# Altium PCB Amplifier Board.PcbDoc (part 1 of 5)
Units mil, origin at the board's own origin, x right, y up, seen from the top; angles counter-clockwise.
Board outline 6000 x 4000 mil, 6 copper layers (Top Layer, GND, VCC, InternalPlane3, InternalPlane4, Bottom Layer); 880 components, 519 nets, 2020 pads, 372 vias.
Unrouted connection lines stored in the file: 585.
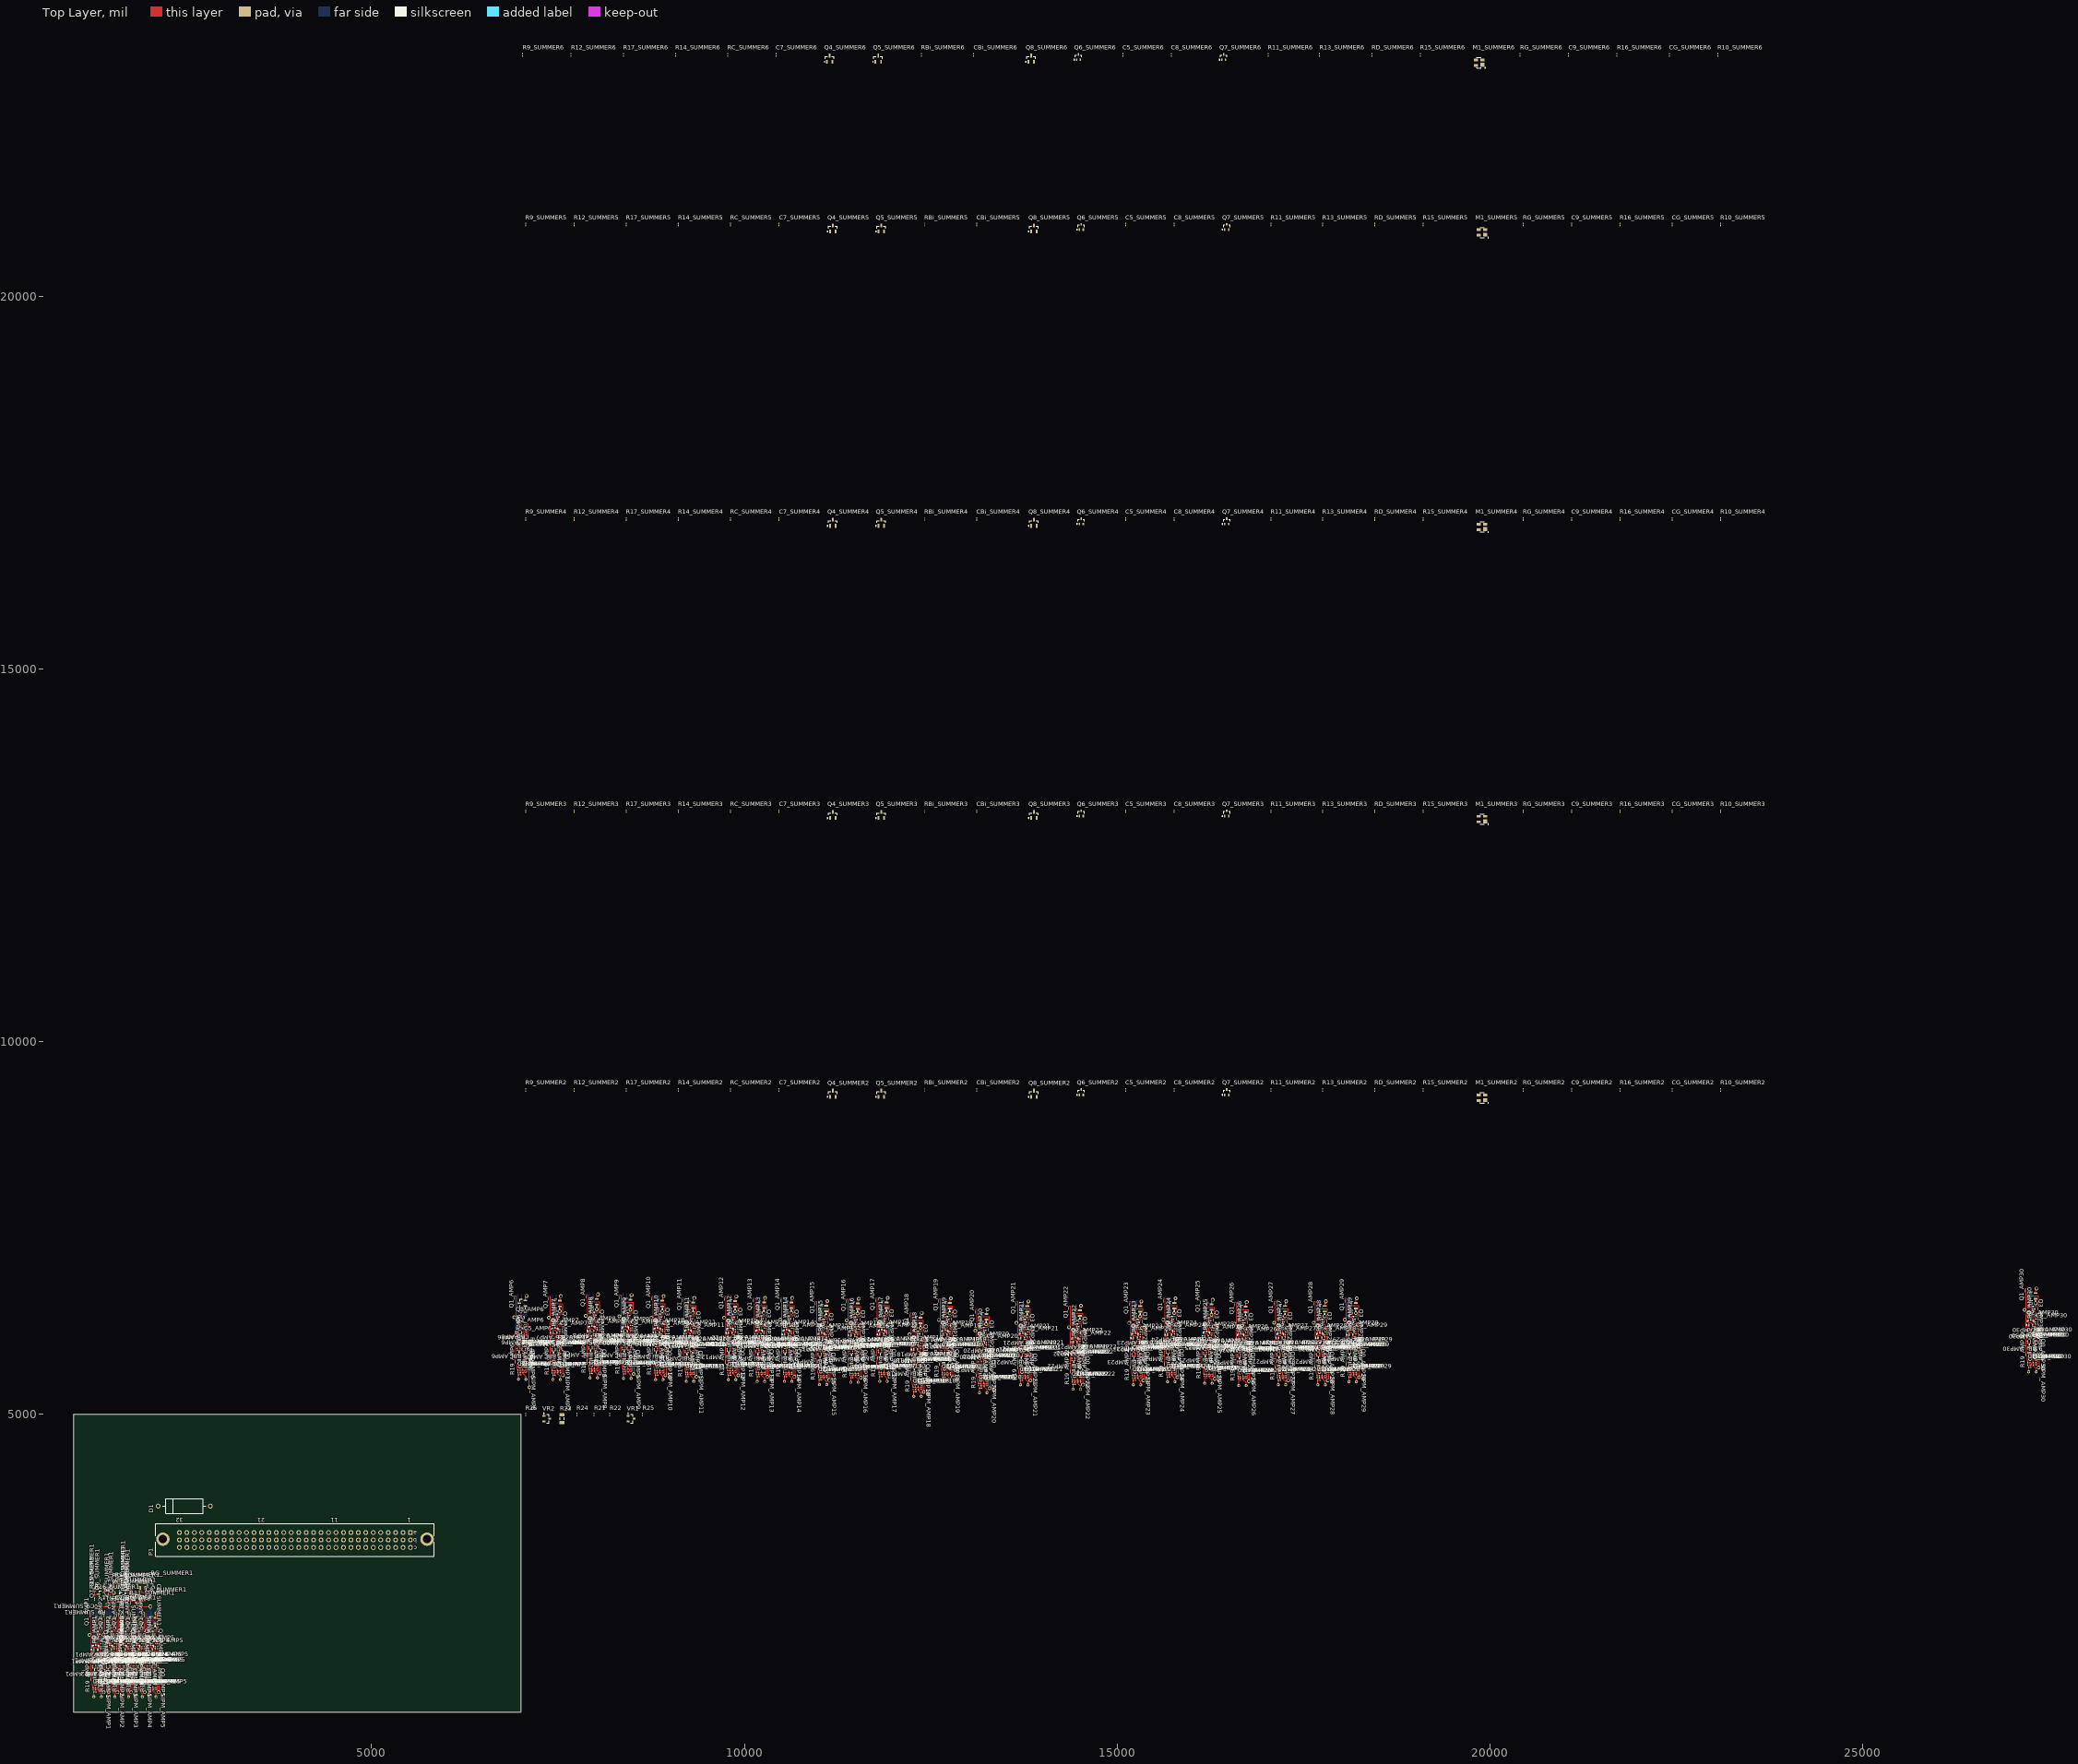
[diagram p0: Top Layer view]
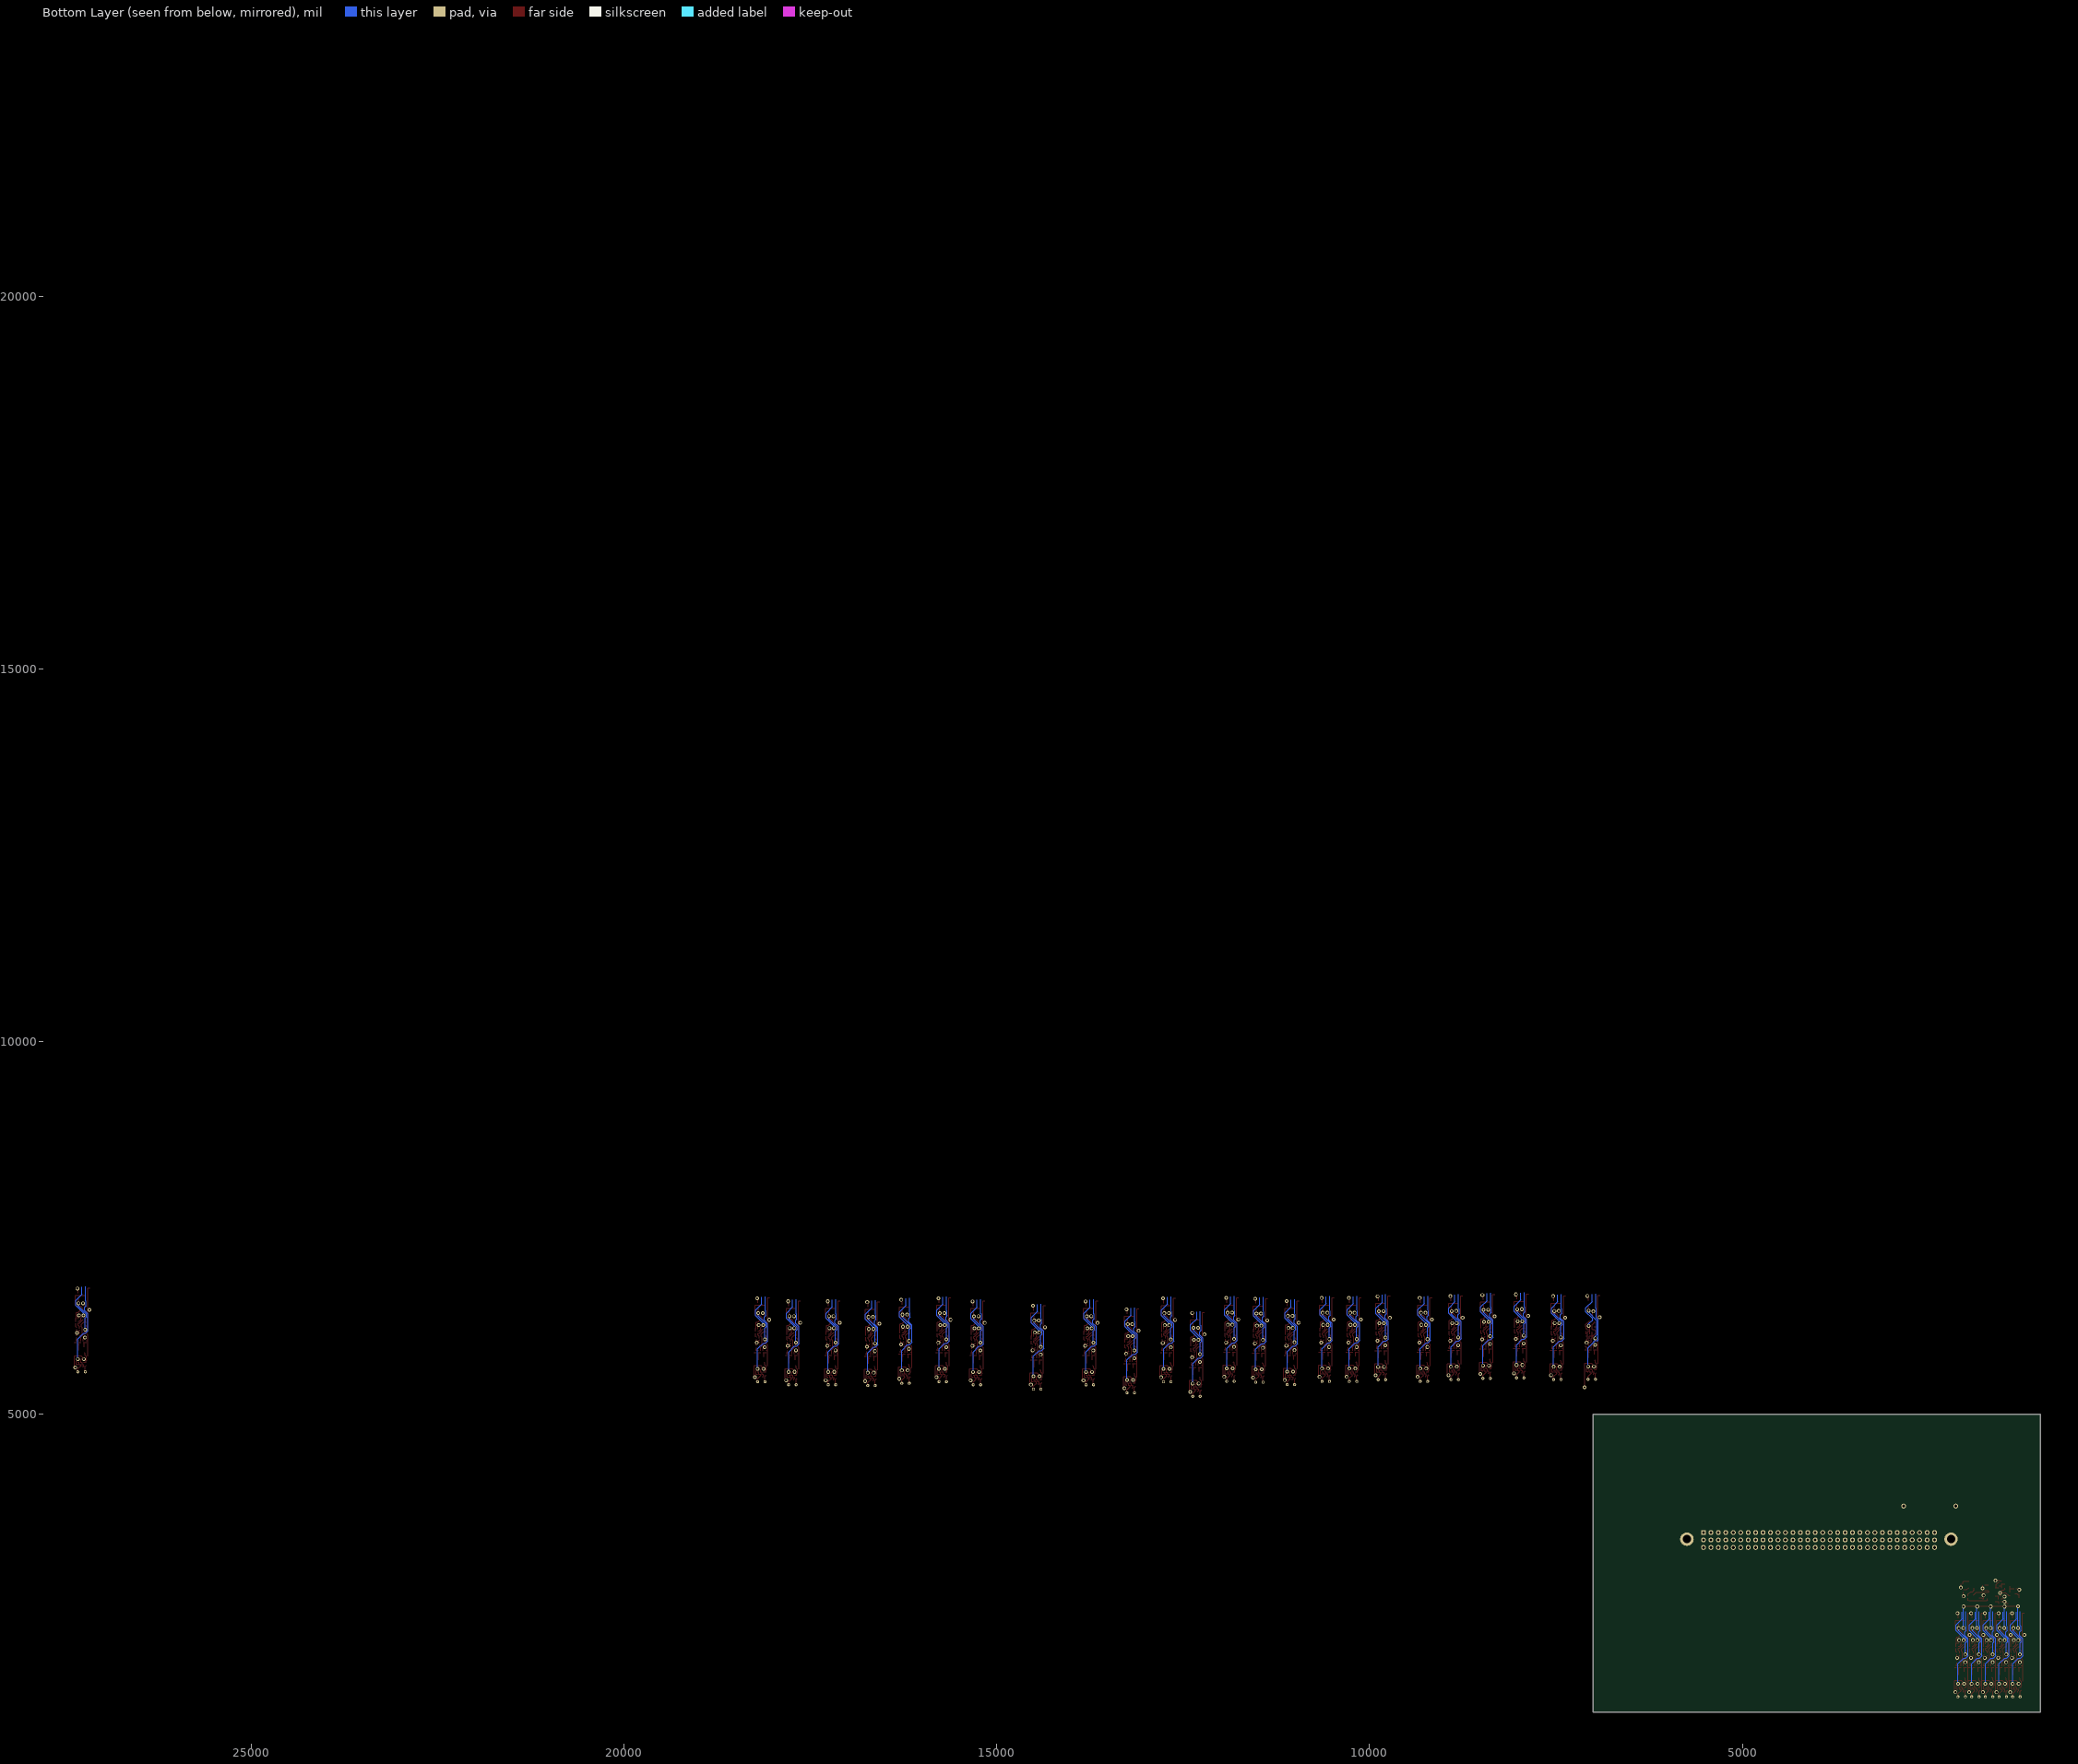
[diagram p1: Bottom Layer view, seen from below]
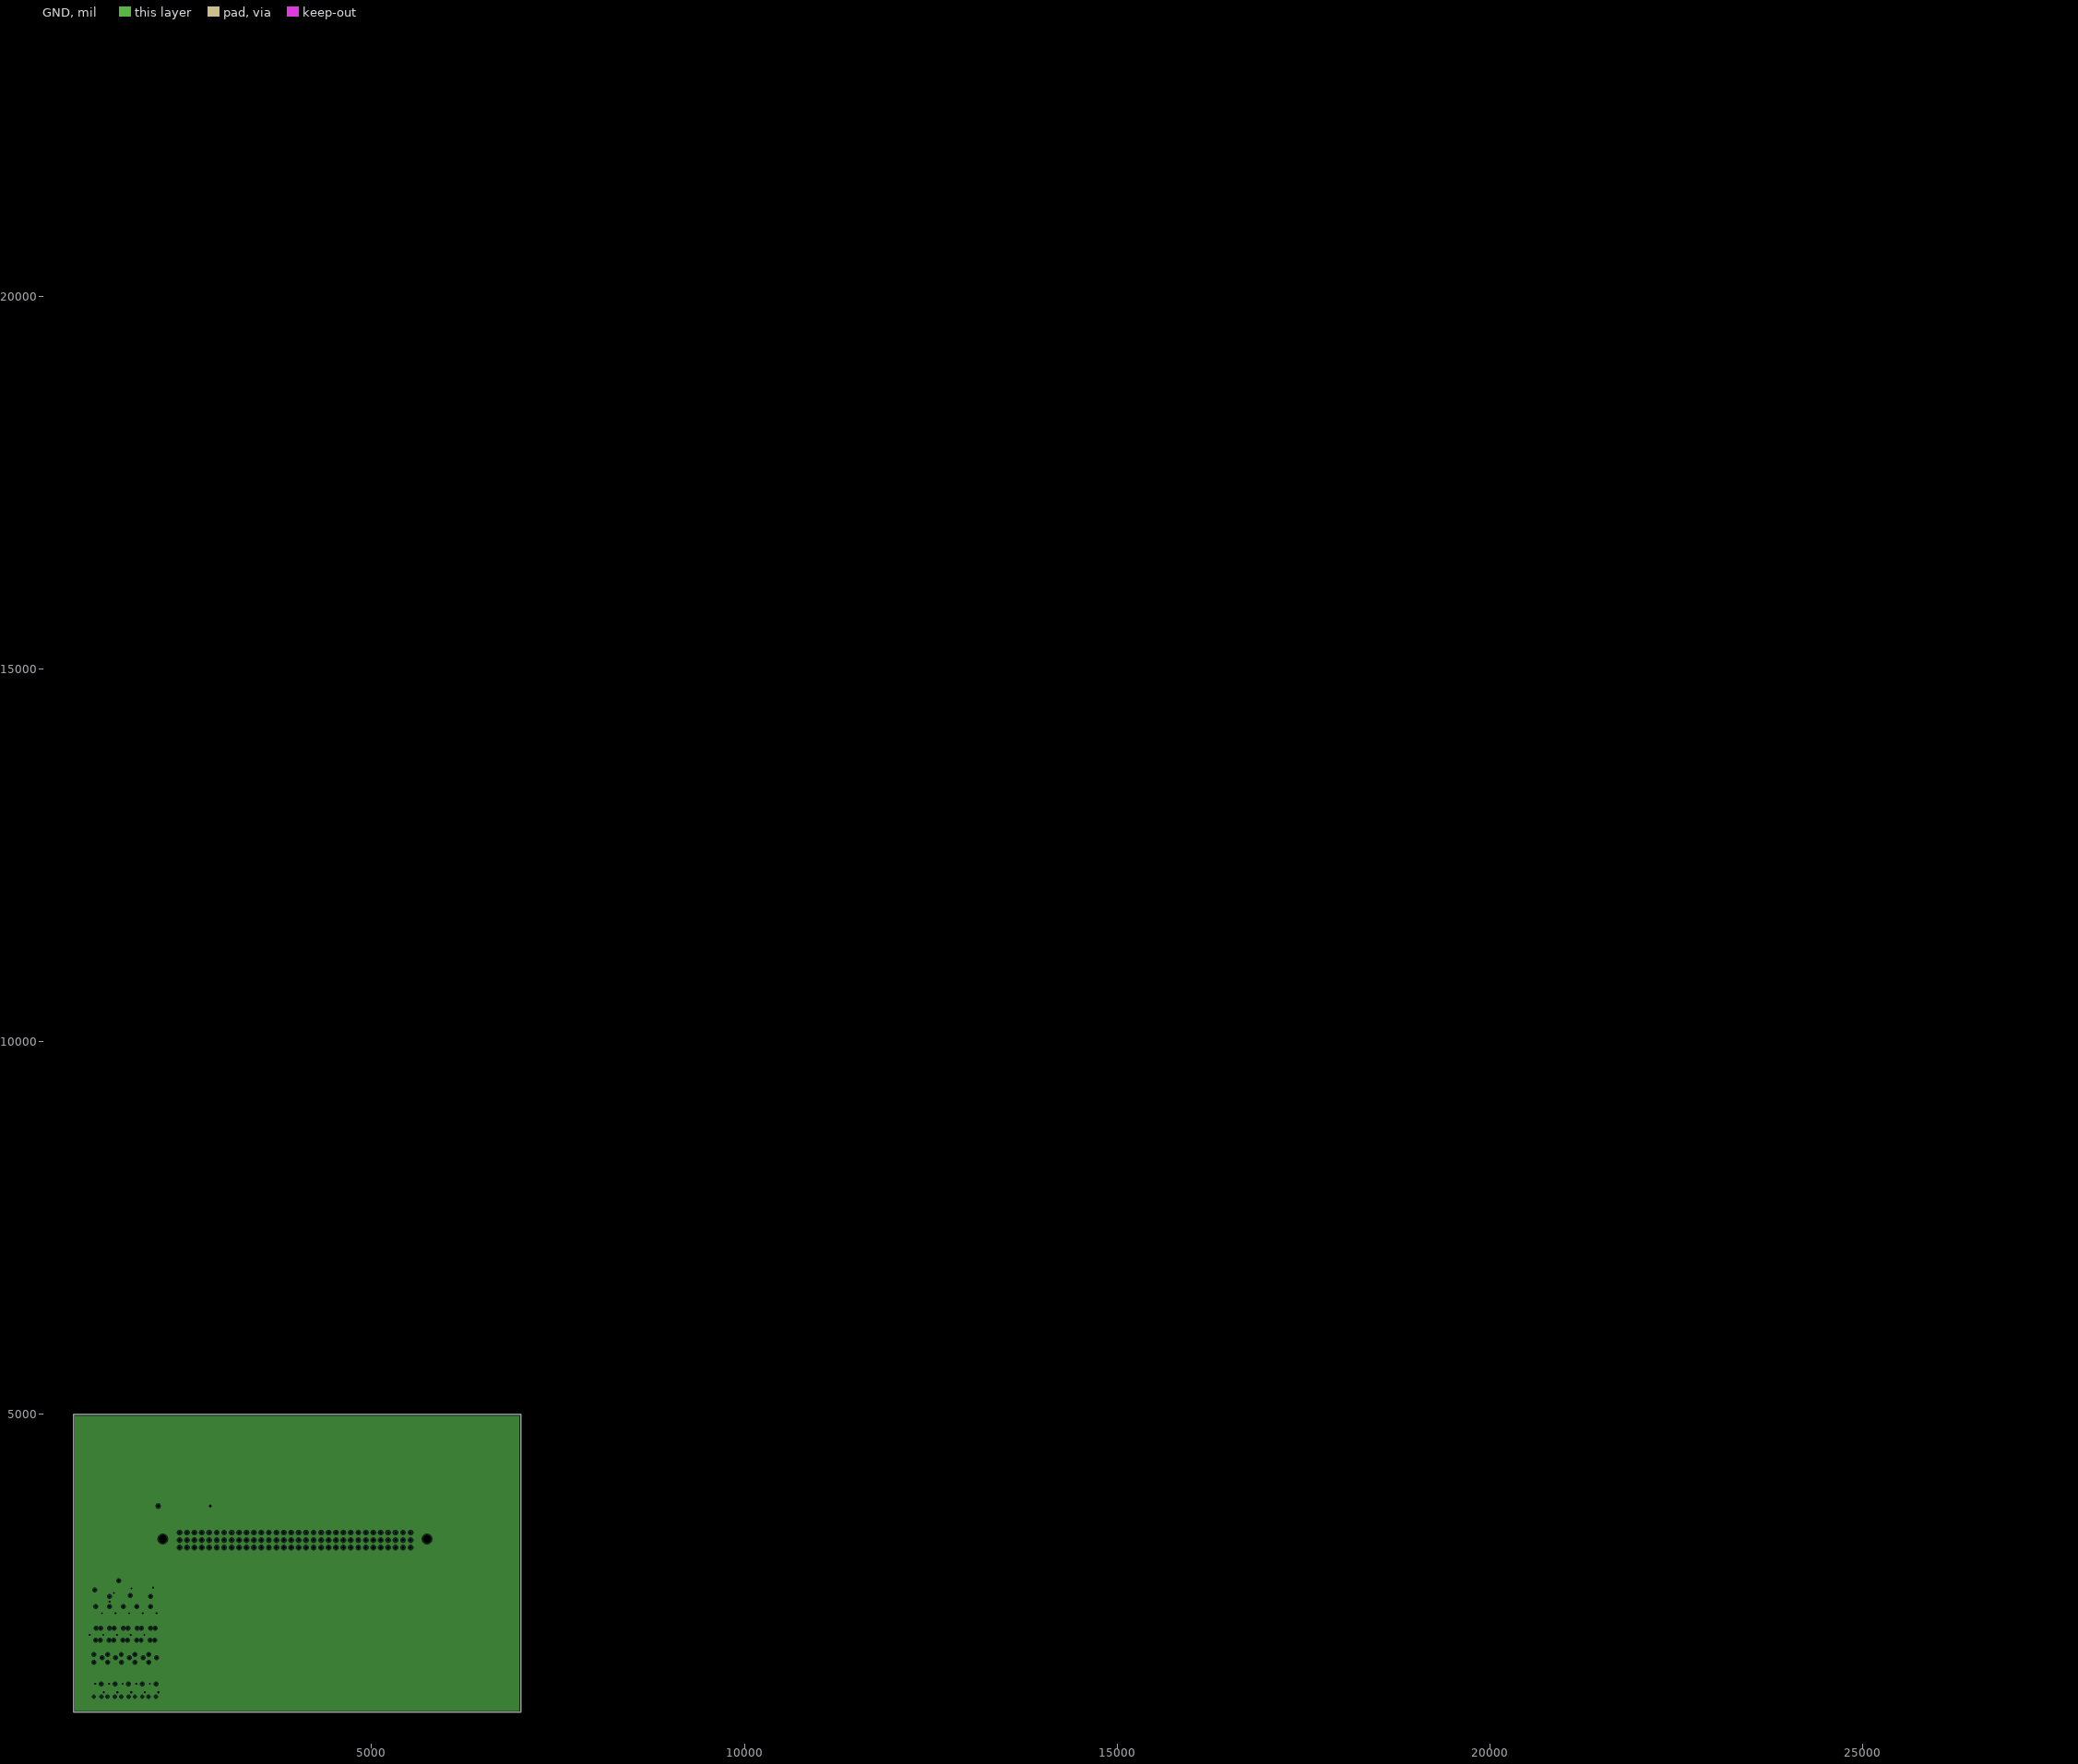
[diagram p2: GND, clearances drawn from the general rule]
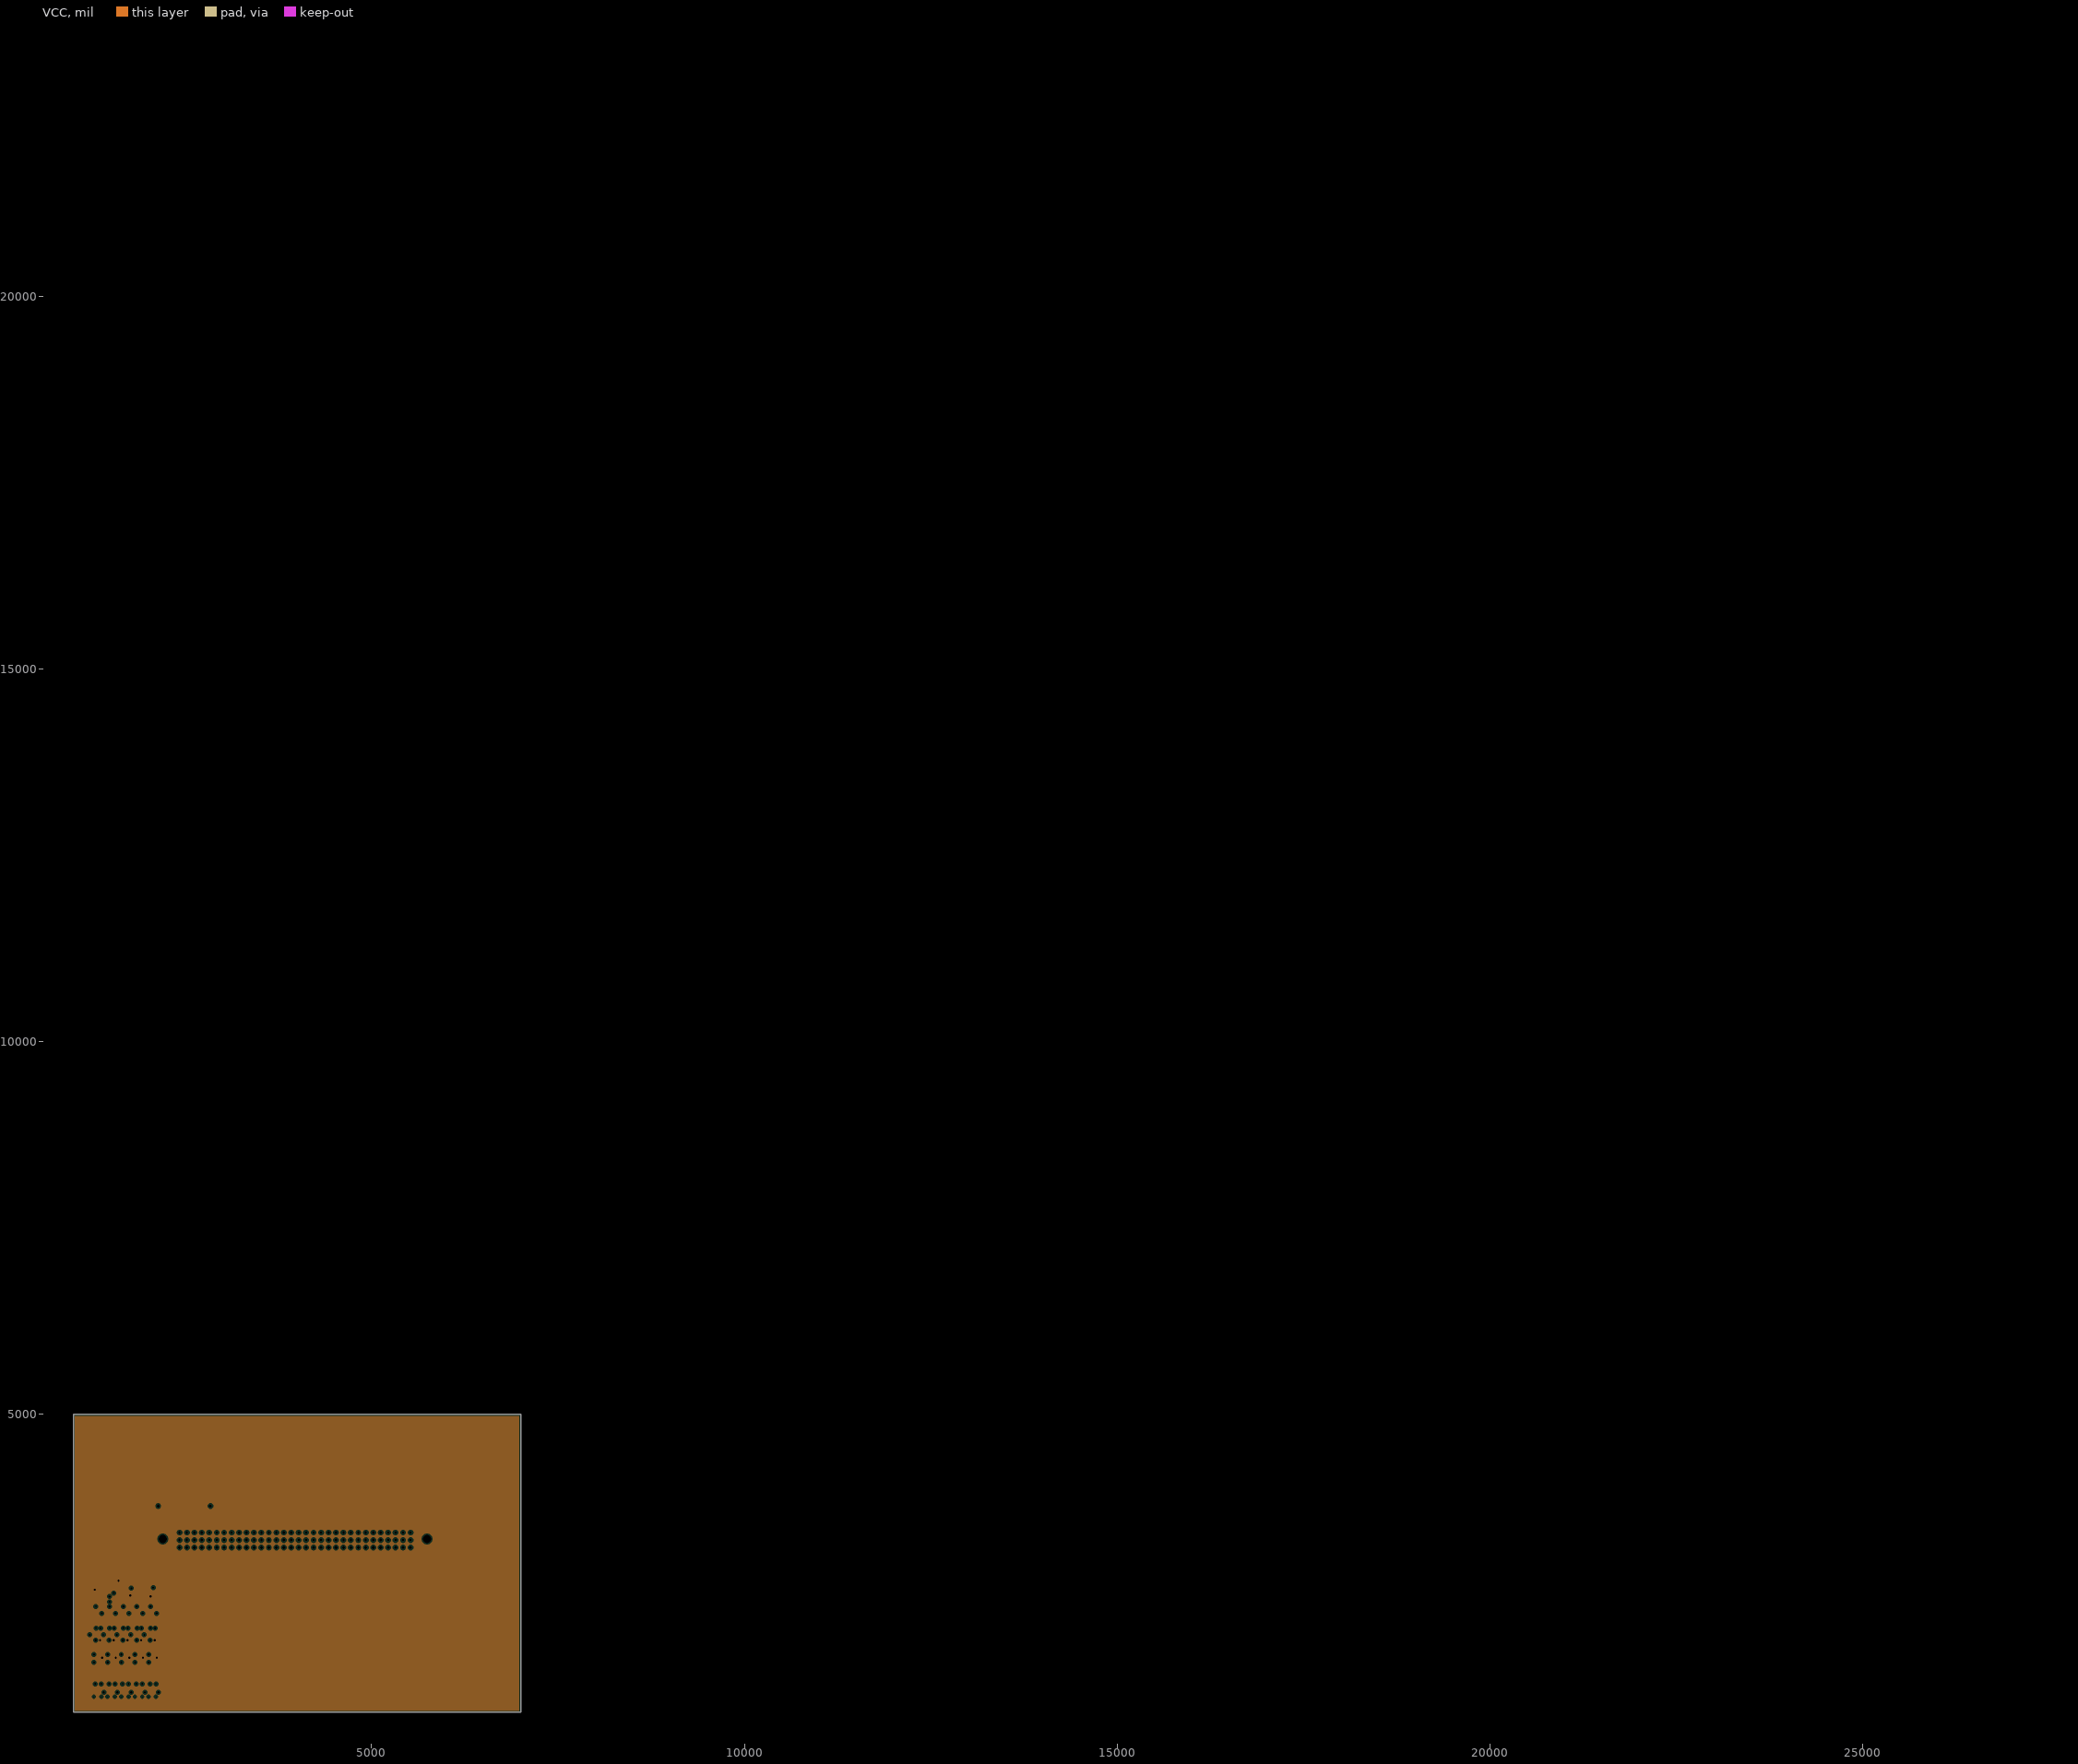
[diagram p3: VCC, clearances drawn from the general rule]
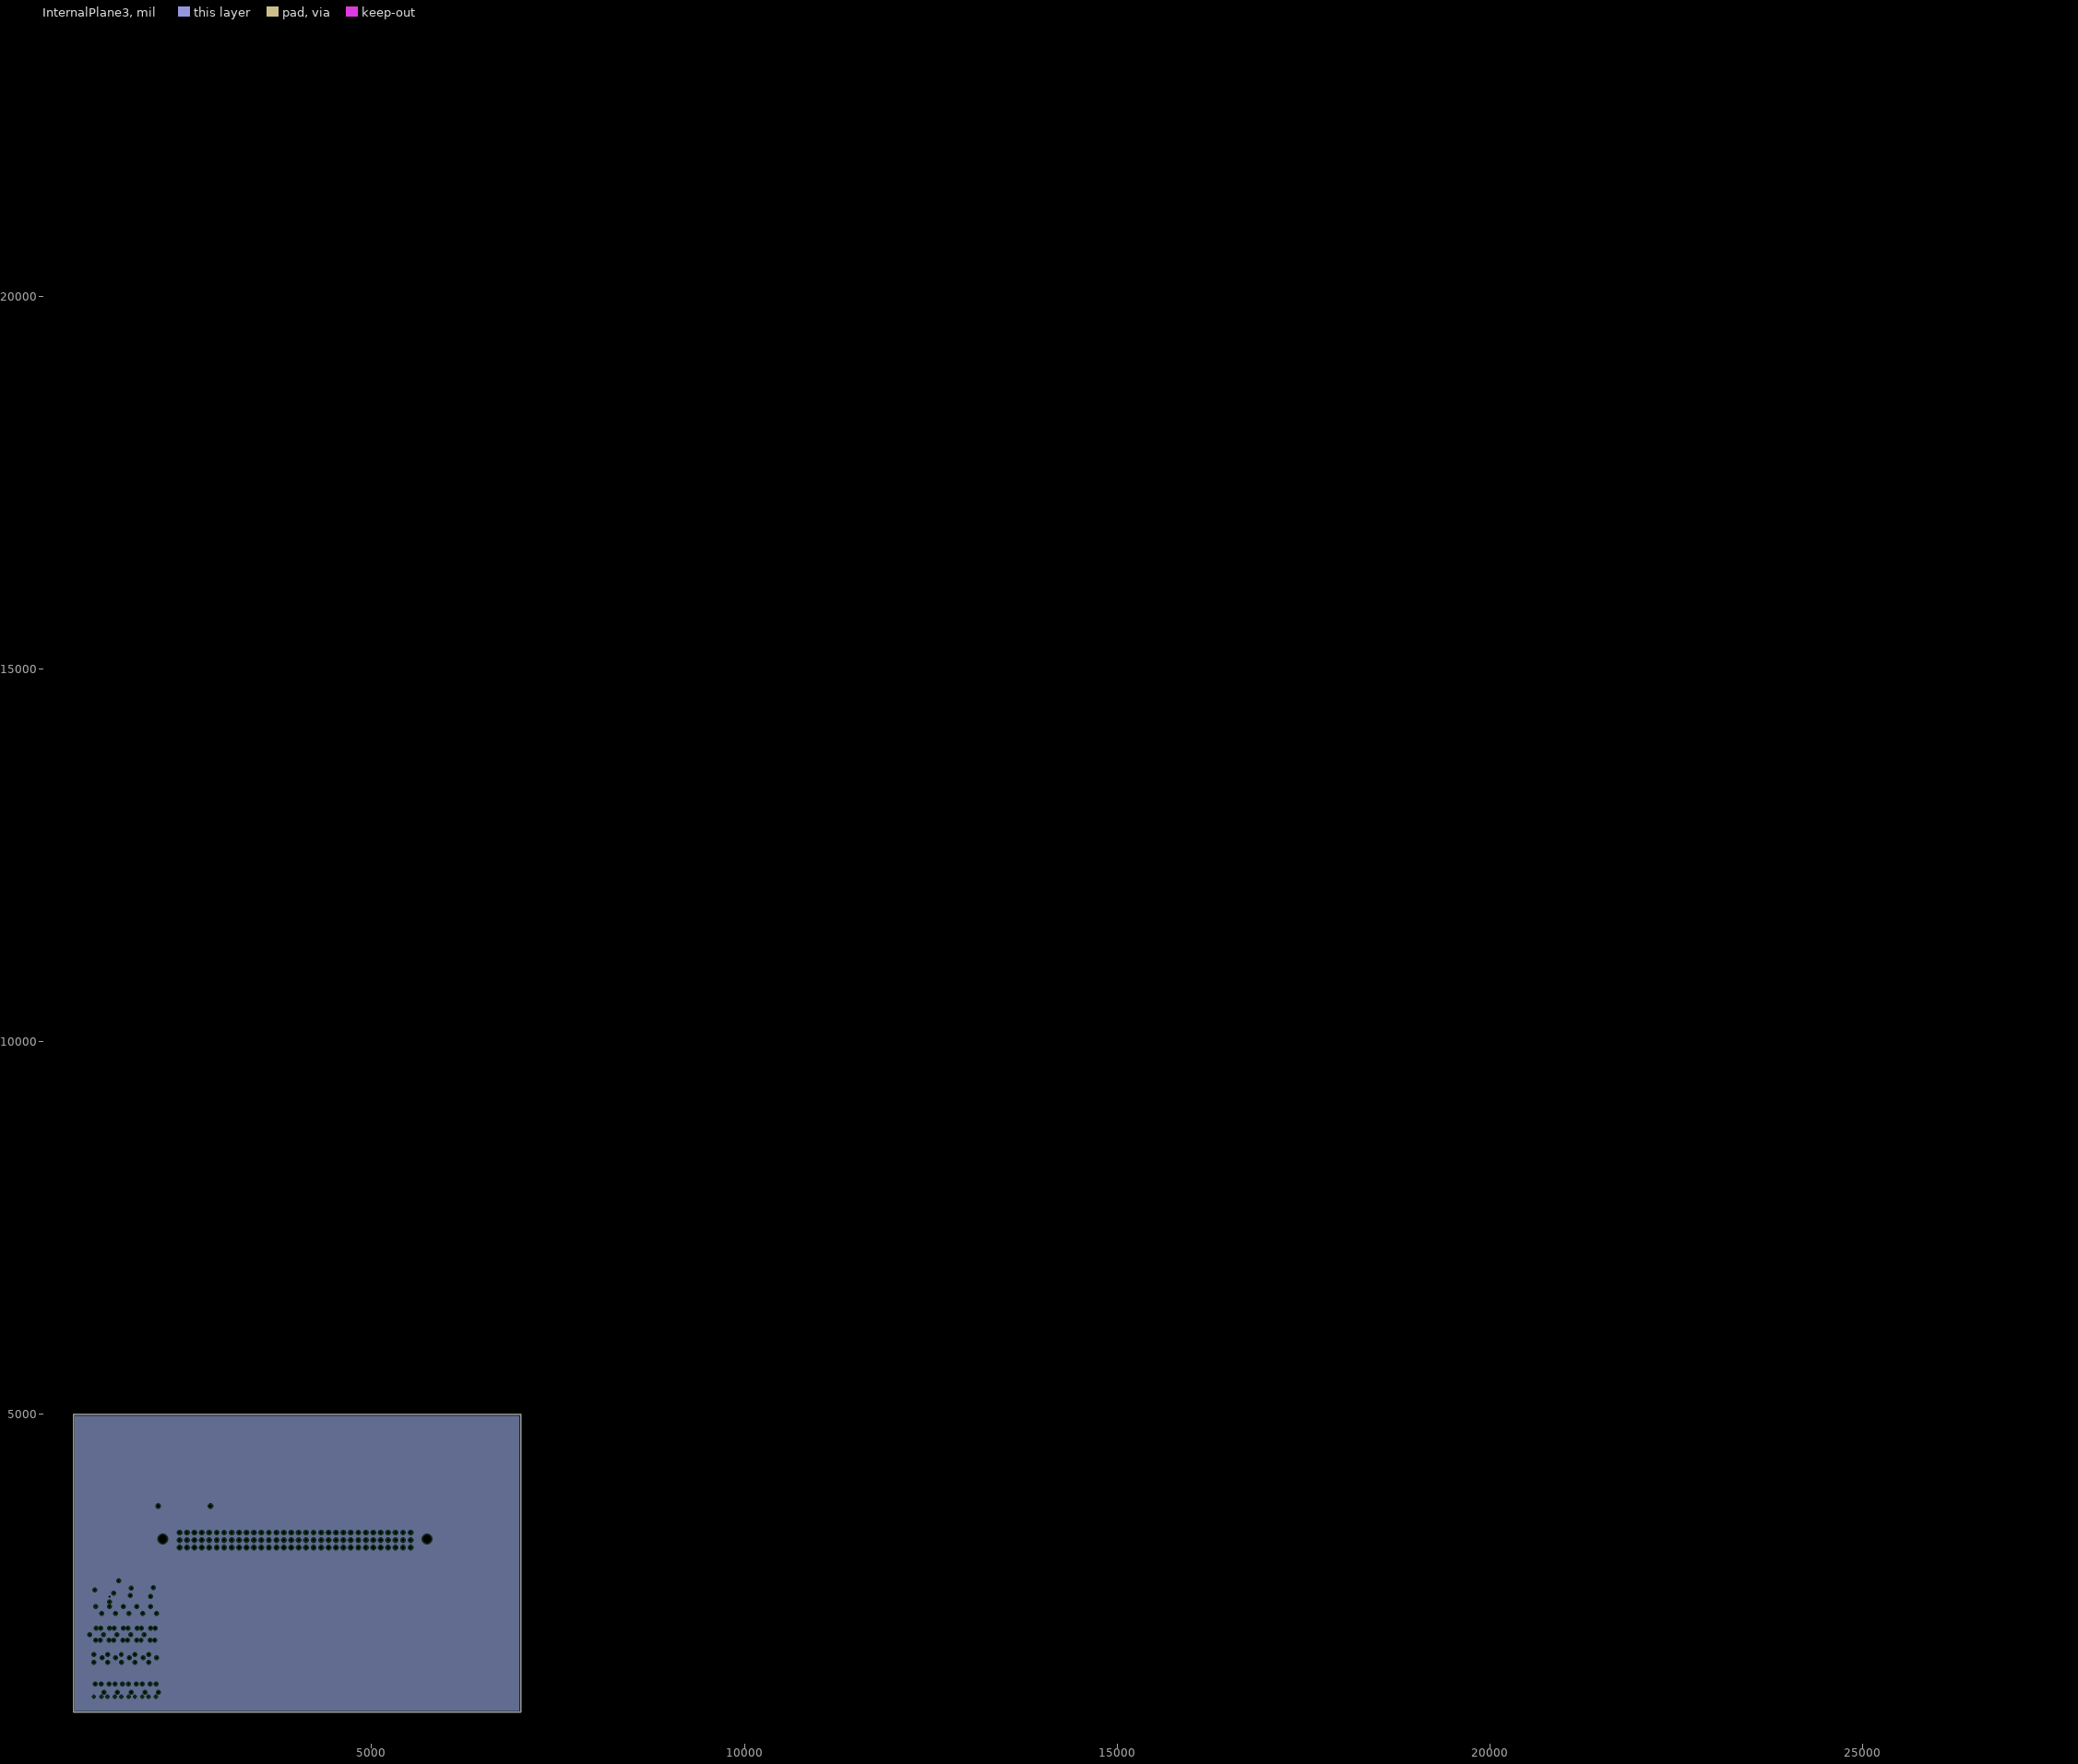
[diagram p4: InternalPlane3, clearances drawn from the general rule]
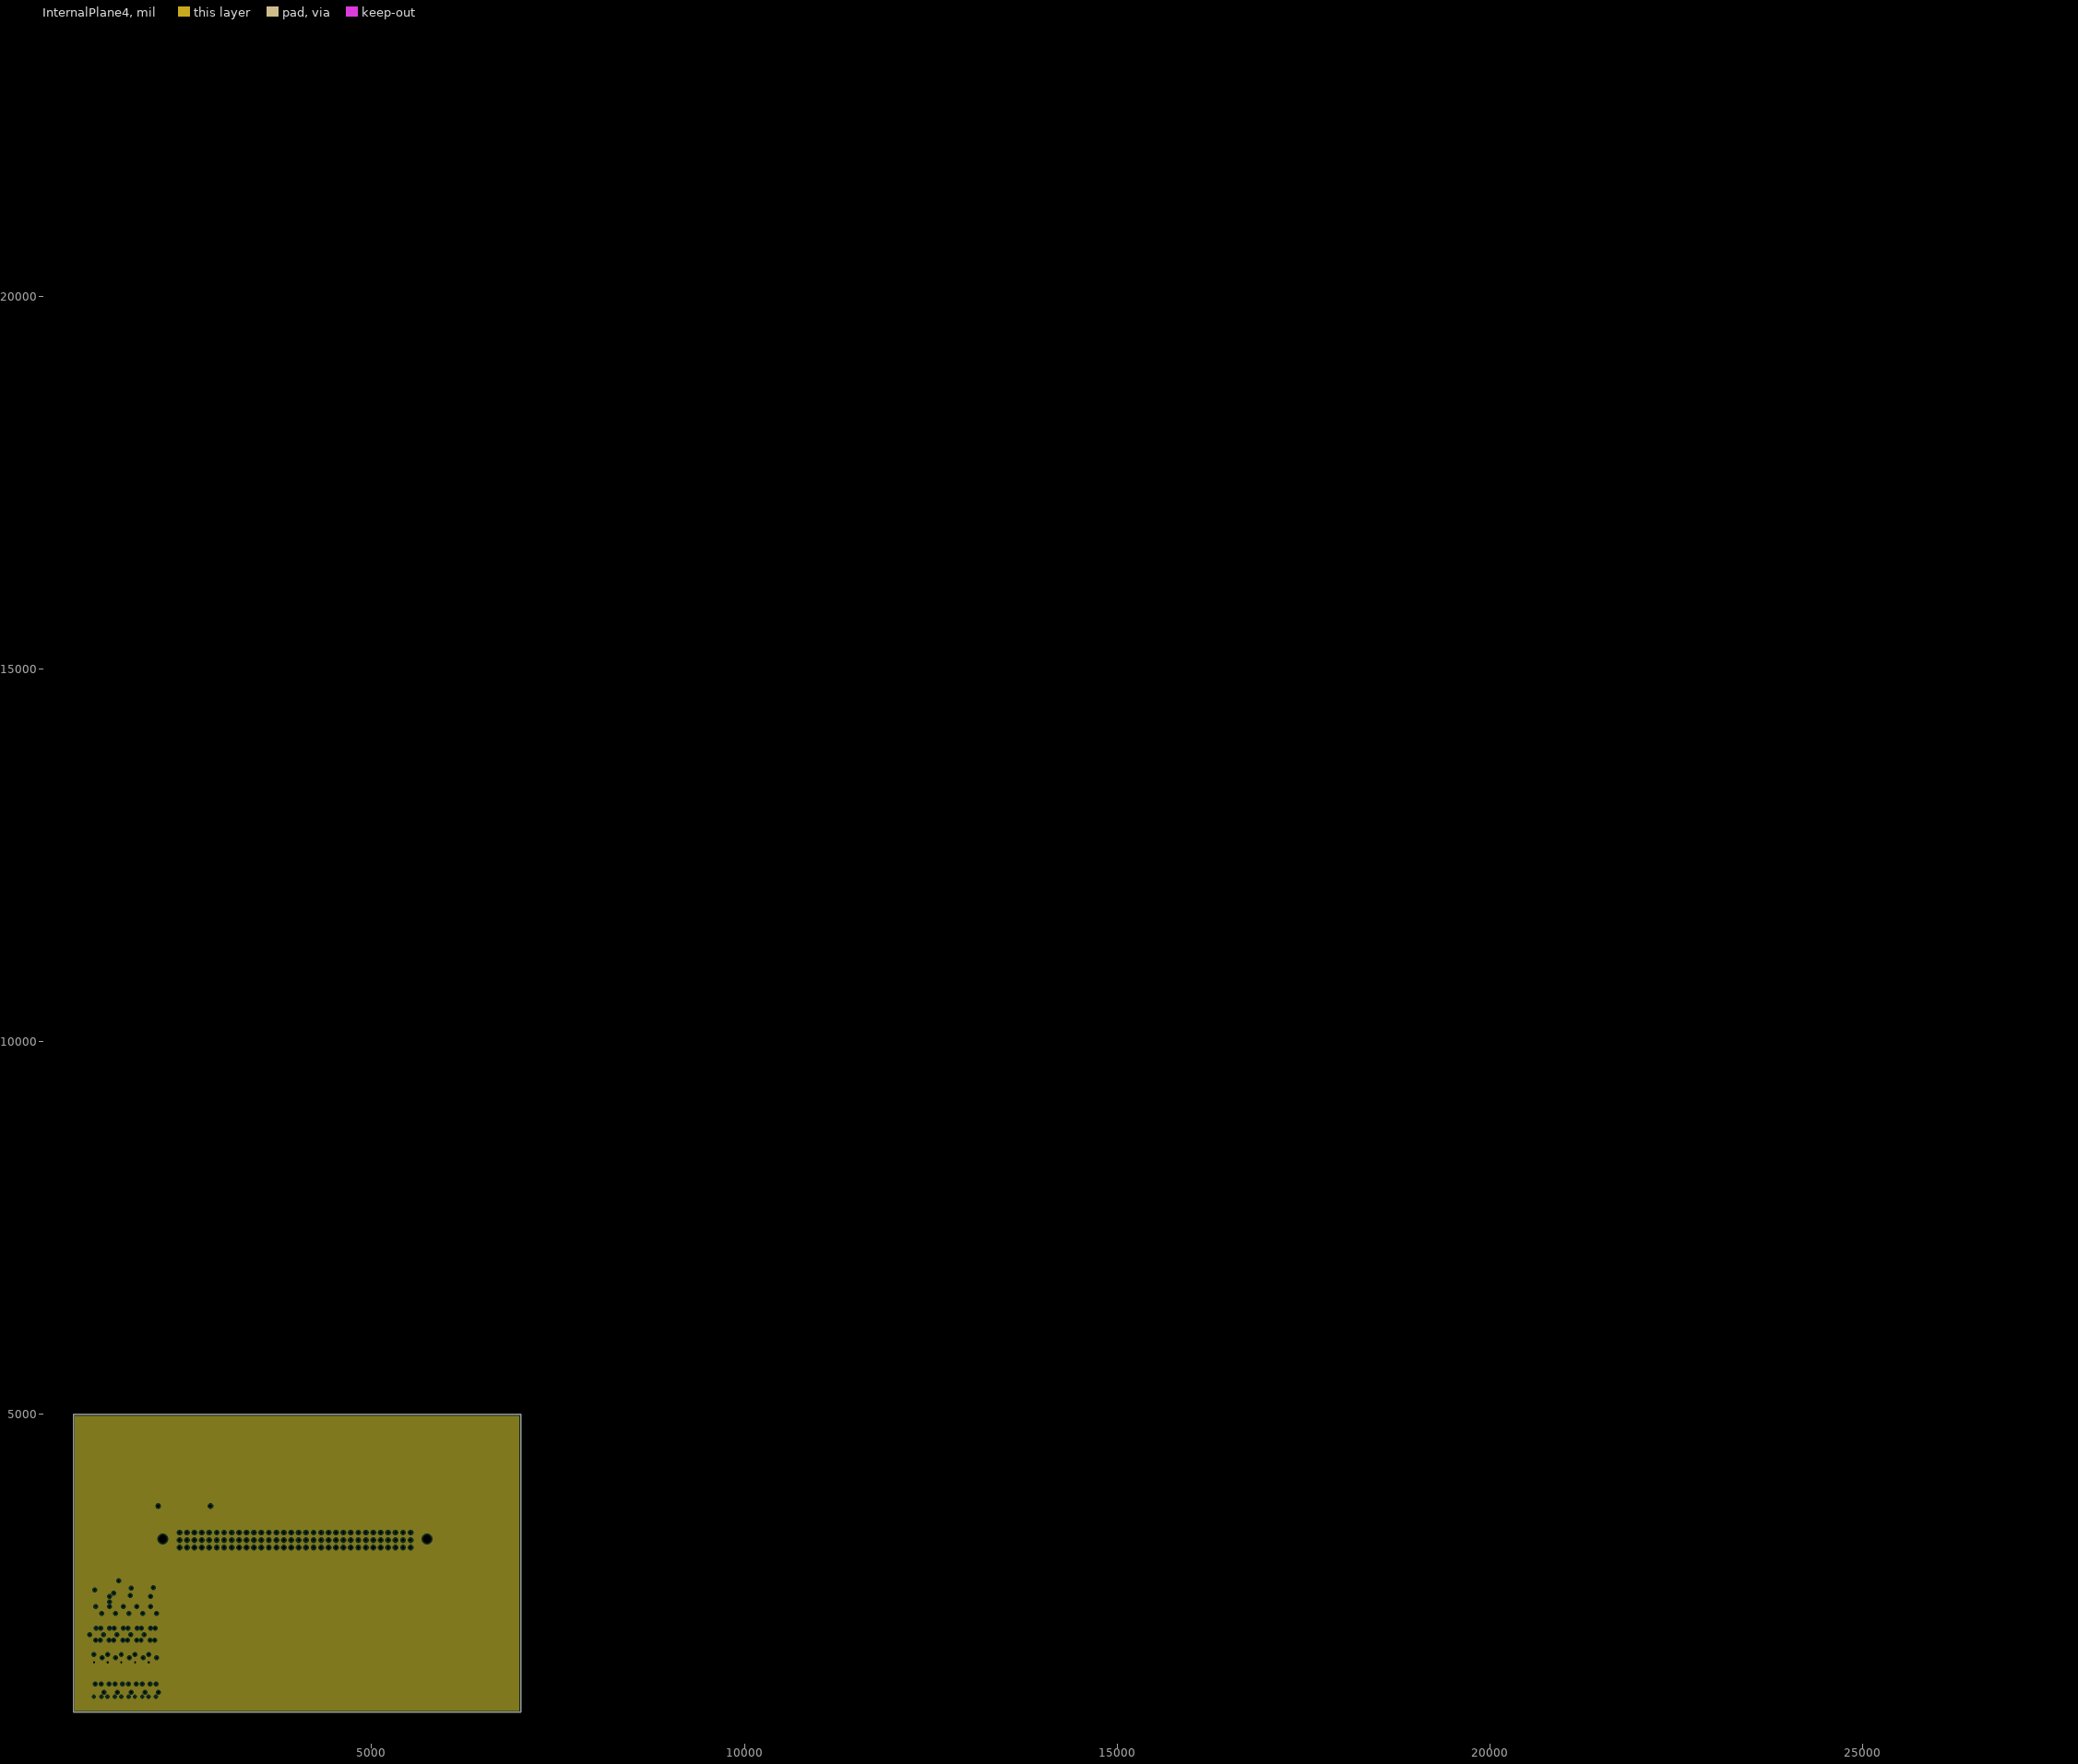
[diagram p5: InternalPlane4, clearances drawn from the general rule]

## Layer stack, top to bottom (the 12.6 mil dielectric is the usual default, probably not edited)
Top Layer: signal copper 1.4
Dielectric: core 12.6, FR-4, Dk 4.8
GND: plane copper 1.4, net GND
Dielectric: prepreg 12.6, FR-4, Dk 4.8
VCC: plane copper 1.4, net VCC
Dielectric: core 12.6, FR-4, Dk 4.8
InternalPlane3: plane copper 1.4, net NetR25_2
Dielectric: prepreg 12.6, FR-4, Dk 4.8
InternalPlane4: plane copper 1.4, net NetR26_2
Dielectric: core 12.6, FR-4, Dk 4.8
Bottom Layer: signal copper 1.4

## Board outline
1000,1000 7000,1000 7000,5000 1000,5000

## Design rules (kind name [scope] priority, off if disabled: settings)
Clearance Clearance_0201 [(HasFootprint('RESC0603L')) vs (HasFootprint('RESC0603L'))] p1: gap=6
Clearance Clearance_General [All] p2: gap=10
ComponentClearance [All] p1: gap=10 collisioncheckmode=3 verticalgap=10
PlaneClearance [All] p1: clearance=20
PlaneConnect [All] p1: planeconnectstyle=Relief reliefexpansion=20 reliefentries=4 reliefconductorwidth=10 reliefairgap=10
PolygonConnect [All] p1: connectstyle=Relief reliefconductorwidth=10 reliefentries=4 polygonreliefangle="90 Angle"
RoomDefinition AMP7 [InComponentClass('AMP7')] p1: confinementstyle=ConfineIn formatcopy=FALSE lockcomponents=FALSE outline 7367,5329 7587,5329 7587,6647 7367,6647
RoomDefinition AMP6 [InComponentClass('AMP6')] p2: confinementstyle=ConfineIn formatcopy=FALSE lockcomponents=FALSE outline 6905,5334 7125,5334 7125,6652 6905,6652
RoomDefinition AMP30 [InComponentClass('AMP30')] p3: confinementstyle=ConfineIn formatcopy=TRUE lockcomponents=FALSE outline 27163,5433 27383,5433 27383,6751 27163,6751
RoomDefinition AMP29 [InComponentClass('AMP29')] p4: confinementstyle=ConfineIn formatcopy=TRUE lockcomponents=FALSE outline 18045,5301 18265,5301 18265,6619 18045,6619
RoomDefinition AMP28 [InComponentClass('AMP28')] p5: confinementstyle=ConfineIn formatcopy=TRUE lockcomponents=FALSE outline 17628,5260 17848,5260 17848,6578 17628,6578
RoomDefinition AMP27 [InComponentClass('AMP27')] p6: confinementstyle=ConfineIn formatcopy=TRUE lockcomponents=FALSE outline 17097,5260 17317,5260 17317,6578 17097,6578
RoomDefinition AMP26 [InComponentClass('AMP26')] p7: confinementstyle=ConfineIn formatcopy=TRUE lockcomponents=FALSE outline 16567,5249 16787,5249 16787,6567 16567,6567
RoomDefinition AMP25 [InComponentClass('AMP25')] p8: confinementstyle=ConfineIn formatcopy=TRUE lockcomponents=FALSE outline 16110,5280 16330,5280 16330,6598 16110,6598
RoomDefinition AMP24 [InComponentClass('AMP24')] p9: confinementstyle=ConfineIn formatcopy=TRUE lockcomponents=FALSE outline 15611,5301 15831,5301 15831,6619 15611,6619
RoomDefinition AMP23 [InComponentClass('AMP23')] p10: confinementstyle=ConfineIn formatcopy=TRUE lockcomponents=FALSE outline 15153,5259 15373,5259 15373,6577 15153,6577
RoomDefinition AMP22 [InComponentClass('AMP22')] p11: confinementstyle=ConfineIn formatcopy=TRUE lockcomponents=FALSE outline 14344,5201 14564,5201 14564,6519 14344,6519
RoomDefinition AMP21 [InComponentClass('AMP21')] p12: confinementstyle=ConfineIn formatcopy=FALSE lockcomponents=FALSE outline 13639,5259 13859,5259 13859,6577 13639,6577
RoomDefinition AMP20 [InComponentClass('AMP20')] p13: confinementstyle=ConfineIn formatcopy=FALSE lockcomponents=FALSE outline 13089,5153 13309,5153 13309,6471 13089,6471
RoomDefinition AMP19 [InComponentClass('AMP19')] p14: confinementstyle=ConfineIn formatcopy=FALSE lockcomponents=FALSE outline 12599,5300 12819,5300 12819,6618 12599,6618
RoomDefinition AMP18 [InComponentClass('AMP18')] p15: confinementstyle=ConfineIn formatcopy=FALSE lockcomponents=FALSE outline 12207,5104 12427,5104 12427,6422 12207,6422
RoomDefinition AMP17 [InComponentClass('AMP17')] p16: confinementstyle=ConfineIn formatcopy=FALSE lockcomponents=FALSE outline 11751,5306 11971,5306 11971,6624 11751,6624
RoomDefinition AMP16 [InComponentClass('AMP16')] p17: confinementstyle=ConfineIn formatcopy=FALSE lockcomponents=FALSE outline 11363,5294 11583,5294 11583,6612 11363,6612
RoomDefinition AMP15 [InComponentClass('AMP15')] p18: confinementstyle=ConfineIn formatcopy=FALSE lockcomponents=FALSE outline 10941,5262 11161,5262 11161,6580 10941,6580
RoomDefinition AMP14 [InComponentClass('AMP14')] p19: confinementstyle=ConfineIn formatcopy=FALSE lockcomponents=FALSE outline 10473,5305 10693,5305 10693,6623 10473,6623
RoomDefinition AMP13 [InComponentClass('AMP13')] p20: confinementstyle=ConfineIn formatcopy=FALSE lockcomponents=FALSE outline 10107,5305 10327,5305 10327,6623 10107,6623
RoomDefinition AMP12 [InComponentClass('AMP12')] p21: confinementstyle=ConfineIn formatcopy=FALSE lockcomponents=FALSE outline 9720,5327 9940,5327 9940,6645 9720,6645
RoomDefinition AMP11 [InComponentClass('AMP11')] p22: confinementstyle=ConfineIn formatcopy=FALSE lockcomponents=FALSE outline 9156,5305 9376,5305 9376,6623 9156,6623
RoomDefinition AMP10 [InComponentClass('AMP10')] p23: confinementstyle=ConfineIn formatcopy=FALSE lockcomponents=FALSE outline 8744,5329 8964,5329 8964,6647 8744,6647
RoomDefinition AMP9 [InComponentClass('AMP9')] p24: confinementstyle=ConfineIn formatcopy=FALSE lockcomponents=FALSE outline 8315,5346 8535,5346 8535,6664 8315,6664
RoomDefinition AMP8 [InComponentClass('AMP8')] p25: confinementstyle=ConfineIn formatcopy=FALSE lockcomponents=FALSE outline 7864,5353 8084,5353 8084,6671 7864,6671
RoomDefinition AMP5 [InComponentClass('AMP5')] p26: confinementstyle=ConfineIn formatcopy=FALSE lockcomponents=FALSE outline 1942,1074 2162,1074 2162,2392 1942,2392
RoomDefinition AMP4 [InComponentClass('AMP4')] p27: confinementstyle=ConfineIn formatcopy=FALSE lockcomponents=FALSE outline 1759,1074 1979,1074 1979,2392 1759,2392
RoomDefinition AMP3 [InComponentClass('AMP3')] p28: confinementstyle=ConfineIn formatcopy=FALSE lockcomponents=FALSE outline 1575,1074 1795,1074 1795,2392 1575,2392
RoomDefinition AMP2 [InComponentClass('AMP2')] p29: confinementstyle=ConfineIn formatcopy=FALSE lockcomponents=TRUE outline 1392,1074 1612,1074 1612,2392 1392,2392
RoomDefinition AMP1 [InComponentClass('AMP1')] p30: confinementstyle=ConfineIn formatcopy=FALSE lockcomponents=FALSE outline 1209,1074 1429,1074 1429,2392 1209,2392
RoomDefinition Main [InComponentClass('Main')] p31: confinementstyle=ConfineIn formatcopy=TRUE lockcomponents=FALSE outline 5852,3082 5852,3877 1992,3877 1992,3082
RoomDefinition SUMMER1 [InComponentClass('SUMMER1')] p32: confinementstyle=ConfineIn formatcopy=TRUE lockcomponents=FALSE outline 1209,2394 2161,2394 2161,2818 1209,2818
RoomDefinition SUMMER2 [InComponentClass('SUMMER2')] p33: confinementstyle=ConfineIn formatcopy=TRUE lockcomponents=FALSE outline 7045,9180 23740,9180 23740,9495 7045,9495
RoomDefinition SUMMER3 [InComponentClass('SUMMER3')] p34: confinementstyle=ConfineIn formatcopy=TRUE lockcomponents=FALSE outline 7045,12920 23740,12920 23740,13235 7045,13235
RoomDefinition SUMMER4 [InComponentClass('SUMMER4')] p35: confinementstyle=ConfineIn formatcopy=TRUE lockcomponents=FALSE outline 7045,16840 23740,16840 23740,17155 7045,17155
RoomDefinition SUMMER5 [InComponentClass('SUMMER5')] p36: confinementstyle=ConfineIn formatcopy=TRUE lockcomponents=FALSE outline 7045,20790 23740,20790 23740,21105 7045,21105
RoomDefinition SUMMER6 [InComponentClass('SUMMER6')] p37: confinementstyle=ConfineIn formatcopy=TRUE lockcomponents=FALSE outline 7006,23068 23701,23068 23701,23383 7006,23383
RoomDefinition VREF [InComponentClass('VREF')] p38: confinementstyle=ConfineIn formatcopy=TRUE lockcomponents=FALSE outline 7045,4850 8810,4850 8810,5130 7045,5130
RoutingVias [All] p1: holewidth=28 width=50 viastyle="Through Hole" minholewidth=28 minwidth=50 maxholewidth=28 maxwidth=50
SolderMaskExpansion [All] p1: expansion=4
TestPointUsage [All] p1: valid=0 allowmultiple=FALSE
Testpoint [All] p1: side=15 testpointundercomponent=TRUE minsize=40 maxsize=100 preferedsize=60 minholesize=0 maxholesize=40 preferedholesize=32 testpointgrid=1 style=1023 order=0123456789
Width [All] p1: maxlimit=10 minlimit=7 preferedwidth=10 toplayer_prefwidth=7 bottomlayer_prefwidth=7 minimp=50.000000 maximp=50.000000 favimp=50.000000
16 further rules are at their usual default settings.

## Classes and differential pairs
channel class Summer: SUMMER1 SUMMER2 SUMMER3 SUMMER4 SUMMER5 SUMMER6
channel class Amplifier: AMP1 AMP2 AMP3 AMP4 AMP5 AMP6 AMP7 AMP8 AMP9 AMP10 AMP11 AMP12 AMP13 AMP14 AMP15 AMP16 AMP17 AMP18 AMP19 AMP20 AMP21 AMP22 AMP23 AMP24 AMP25 AMP26 AMP27 AMP28 AMP29 AMP30
net class SUMMEDOUT_SUMMER[1..6]: SUMMEDOUT_SUMMER1 SUMMEDOUT_SUMMER2 SUMMEDOUT_SUMMER3 SUMMEDOUT_SUMMER4 SUMMEDOUT_SUMMER5 SUMMEDOUT_SUMMER6
component class VREF: R21 R22 R23 R24 R25 R26 VR1 VR2
component class SUMMER6: C5_SUMMER6 C7_SUMMER6 C8_SUMMER6 C9_SUMMER6 CBi_SUMMER6 CG_SUMMER6 M1_SUMMER6 Q4_SUMMER6 Q5_SUMMER6 Q6_SUMMER6 Q7_SUMMER6 Q8_SUMMER6 R9_SUMMER6 R10_SUMMER6 R11_SUMMER6 R12_SUMMER6 R13_SUMMER6 R14_SUMMER6 R15_SUMMER6 R16_SUMMER6 R17_SUMMER6 RBi_SUMMER6 RC_SUMMER6 RD_SUMMER6 RG_SUMMER6
component class SUMMER5: C5_SUMMER5 C7_SUMMER5 C8_SUMMER5 C9_SUMMER5 CBi_SUMMER5 CG_SUMMER5 M1_SUMMER5 Q4_SUMMER5 Q5_SUMMER5 Q6_SUMMER5 Q7_SUMMER5 Q8_SUMMER5 R9_SUMMER5 R10_SUMMER5 R11_SUMMER5 R12_SUMMER5 R13_SUMMER5 R14_SUMMER5 R15_SUMMER5 R16_SUMMER5 R17_SUMMER5 RBi_SUMMER5 RC_SUMMER5 RD_SUMMER5 RG_SUMMER5
component class SUMMER4: C5_SUMMER4 C7_SUMMER4 C8_SUMMER4 C9_SUMMER4 CBi_SUMMER4 CG_SUMMER4 M1_SUMMER4 Q4_SUMMER4 Q5_SUMMER4 Q6_SUMMER4 Q7_SUMMER4 Q8_SUMMER4 R9_SUMMER4 R10_SUMMER4 R11_SUMMER4 R12_SUMMER4 R13_SUMMER4 R14_SUMMER4 R15_SUMMER4 R16_SUMMER4 R17_SUMMER4 RBi_SUMMER4 RC_SUMMER4 RD_SUMMER4 RG_SUMMER4
component class SUMMER3: C5_SUMMER3 C7_SUMMER3 C8_SUMMER3 C9_SUMMER3 CBi_SUMMER3 CG_SUMMER3 M1_SUMMER3 Q4_SUMMER3 Q5_SUMMER3 Q6_SUMMER3 Q7_SUMMER3 Q8_SUMMER3 R9_SUMMER3 R10_SUMMER3 R11_SUMMER3 R12_SUMMER3 R13_SUMMER3 R14_SUMMER3 R15_SUMMER3 R16_SUMMER3 R17_SUMMER3 RBi_SUMMER3 RC_SUMMER3 RD_SUMMER3 RG_SUMMER3
component class SUMMER2: C5_SUMMER2 C7_SUMMER2 C8_SUMMER2 C9_SUMMER2 CBi_SUMMER2 CG_SUMMER2 M1_SUMMER2 Q4_SUMMER2 Q5_SUMMER2 Q6_SUMMER2 Q7_SUMMER2 Q8_SUMMER2 R9_SUMMER2 R10_SUMMER2 R11_SUMMER2 R12_SUMMER2 R13_SUMMER2 R14_SUMMER2 R15_SUMMER2 R16_SUMMER2 R17_SUMMER2 RBi_SUMMER2 RC_SUMMER2 RD_SUMMER2 RG_SUMMER2
component class SUMMER1: C5_SUMMER1 C7_SUMMER1 C8_SUMMER1 C9_SUMMER1 CBi_SUMMER1 CG_SUMMER1 M1_SUMMER1 Q4_SUMMER1 Q5_SUMMER1 Q6_SUMMER1 Q7_SUMMER1 Q8_SUMMER1 R9_SUMMER1 R10_SUMMER1 R11_SUMMER1 R12_SUMMER1 R13_SUMMER1 R14_SUMMER1 R15_SUMMER1 R16_SUMMER1 R17_SUMMER1 RBi_SUMMER1 RC_SUMMER1 RD_SUMMER1 RG_SUMMER1
component class Main: D1 P1
component class AMP30: C1_AMP30 C2_AMP30 C3_AMP30 C4_AMP30 C5_AMP30 C6_AMP30 CBi_AMP30 Q0_AMP30 Q1_AMP30 Q2_AMP30 Q3_AMP30 R1_AMP30 R2_AMP30 R3_AMP30 R4_AMP30 R5_AMP30 R6_AMP30 R7_AMP30 R8_AMP30 R18_AMP30 R19_AMP30 R20_AMP30 RBi_AMP30 SIPM_AMP30
component class AMP29: C1_AMP29 C2_AMP29 C3_AMP29 C4_AMP29 C5_AMP29 C6_AMP29 CBi_AMP29 Q0_AMP29 Q1_AMP29 Q2_AMP29 Q3_AMP29 R1_AMP29 R2_AMP29 R3_AMP29 R4_AMP29 R5_AMP29 R6_AMP29 R7_AMP29 R8_AMP29 R18_AMP29 R19_AMP29 R20_AMP29 RBi_AMP29 SIPM_AMP29
component class AMP28: C1_AMP28 C2_AMP28 C3_AMP28 C4_AMP28 C5_AMP28 C6_AMP28 CBi_AMP28 Q0_AMP28 Q1_AMP28 Q2_AMP28 Q3_AMP28 R1_AMP28 R2_AMP28 R3_AMP28 R4_AMP28 R5_AMP28 R6_AMP28 R7_AMP28 R8_AMP28 R18_AMP28 R19_AMP28 R20_AMP28 RBi_AMP28 SIPM_AMP28
component class AMP27: C1_AMP27 C2_AMP27 C3_AMP27 C4_AMP27 C5_AMP27 C6_AMP27 CBi_AMP27 Q0_AMP27 Q1_AMP27 Q2_AMP27 Q3_AMP27 R1_AMP27 R2_AMP27 R3_AMP27 R4_AMP27 R5_AMP27 R6_AMP27 R7_AMP27 R8_AMP27 R18_AMP27 R19_AMP27 R20_AMP27 RBi_AMP27 SIPM_AMP27
component class AMP26: C1_AMP26 C2_AMP26 C3_AMP26 C4_AMP26 C5_AMP26 C6_AMP26 CBi_AMP26 Q0_AMP26 Q1_AMP26 Q2_AMP26 Q3_AMP26 R1_AMP26 R2_AMP26 R3_AMP26 R4_AMP26 R5_AMP26 R6_AMP26 R7_AMP26 R8_AMP26 R18_AMP26 R19_AMP26 R20_AMP26 RBi_AMP26 SIPM_AMP26
component class AMP25: C1_AMP25 C2_AMP25 C3_AMP25 C4_AMP25 C5_AMP25 C6_AMP25 CBi_AMP25 Q0_AMP25 Q1_AMP25 Q2_AMP25 Q3_AMP25 R1_AMP25 R2_AMP25 R3_AMP25 R4_AMP25 R5_AMP25 R6_AMP25 R7_AMP25 R8_AMP25 R18_AMP25 R19_AMP25 R20_AMP25 RBi_AMP25 SIPM_AMP25
component class AMP24: C1_AMP24 C2_AMP24 C3_AMP24 C4_AMP24 C5_AMP24 C6_AMP24 CBi_AMP24 Q0_AMP24 Q1_AMP24 Q2_AMP24 Q3_AMP24 R1_AMP24 R2_AMP24 R3_AMP24 R4_AMP24 R5_AMP24 R6_AMP24 R7_AMP24 R8_AMP24 R18_AMP24 R19_AMP24 R20_AMP24 RBi_AMP24 SIPM_AMP24
component class AMP23: C1_AMP23 C2_AMP23 C3_AMP23 C4_AMP23 C5_AMP23 C6_AMP23 CBi_AMP23 Q0_AMP23 Q1_AMP23 Q2_AMP23 Q3_AMP23 R1_AMP23 R2_AMP23 R3_AMP23 R4_AMP23 R5_AMP23 R6_AMP23 R7_AMP23 R8_AMP23 R18_AMP23 R19_AMP23 R20_AMP23 RBi_AMP23 SIPM_AMP23
component class AMP22: C1_AMP22 C2_AMP22 C3_AMP22 C4_AMP22 C5_AMP22 C6_AMP22 CBi_AMP22 Q0_AMP22 Q1_AMP22 Q2_AMP22 Q3_AMP22 R1_AMP22 R2_AMP22 R3_AMP22 R4_AMP22 R5_AMP22 R6_AMP22 R7_AMP22 R8_AMP22 R18_AMP22 R19_AMP22 R20_AMP22 RBi_AMP22 SIPM_AMP22
component class AMP21: C1_AMP21 C2_AMP21 C3_AMP21 C4_AMP21 C5_AMP21 C6_AMP21 CBi_AMP21 Q0_AMP21 Q1_AMP21 Q2_AMP21 Q3_AMP21 R1_AMP21 R2_AMP21 R3_AMP21 R4_AMP21 R5_AMP21 R6_AMP21 R7_AMP21 R8_AMP21 R18_AMP21 R19_AMP21 R20_AMP21 RBi_AMP21 SIPM_AMP21
component class AMP20: C1_AMP20 C2_AMP20 C3_AMP20 C4_AMP20 C5_AMP20 C6_AMP20 CBi_AMP20 Q0_AMP20 Q1_AMP20 Q2_AMP20 Q3_AMP20 R1_AMP20 R2_AMP20 R3_AMP20 R4_AMP20 R5_AMP20 R6_AMP20 R7_AMP20 R8_AMP20 R18_AMP20 R19_AMP20 R20_AMP20 RBi_AMP20 SIPM_AMP20
component class AMP19: C1_AMP19 C2_AMP19 C3_AMP19 C4_AMP19 C5_AMP19 C6_AMP19 CBi_AMP19 Q0_AMP19 Q1_AMP19 Q2_AMP19 Q3_AMP19 R1_AMP19 R2_AMP19 R3_AMP19 R4_AMP19 R5_AMP19 R6_AMP19 R7_AMP19 R8_AMP19 R18_AMP19 R19_AMP19 R20_AMP19 RBi_AMP19 SIPM_AMP19
component class AMP18: C1_AMP18 C2_AMP18 C3_AMP18 C4_AMP18 C5_AMP18 C6_AMP18 CBi_AMP18 Q0_AMP18 Q1_AMP18 Q2_AMP18 Q3_AMP18 R1_AMP18 R2_AMP18 R3_AMP18 R4_AMP18 R5_AMP18 R6_AMP18 R7_AMP18 R8_AMP18 R18_AMP18 R19_AMP18 R20_AMP18 RBi_AMP18 SIPM_AMP18
component class AMP17: C1_AMP17 C2_AMP17 C3_AMP17 C4_AMP17 C5_AMP17 C6_AMP17 CBi_AMP17 Q0_AMP17 Q1_AMP17 Q2_AMP17 Q3_AMP17 R1_AMP17 R2_AMP17 R3_AMP17 R4_AMP17 R5_AMP17 R6_AMP17 R7_AMP17 R8_AMP17 R18_AMP17 R19_AMP17 R20_AMP17 RBi_AMP17 SIPM_AMP17
component class AMP16: C1_AMP16 C2_AMP16 C3_AMP16 C4_AMP16 C5_AMP16 C6_AMP16 CBi_AMP16 Q0_AMP16 Q1_AMP16 Q2_AMP16 Q3_AMP16 R1_AMP16 R2_AMP16 R3_AMP16 R4_AMP16 R5_AMP16 R6_AMP16 R7_AMP16 R8_AMP16 R18_AMP16 R19_AMP16 R20_AMP16 RBi_AMP16 SIPM_AMP16
component class AMP15: C1_AMP15 C2_AMP15 C3_AMP15 C4_AMP15 C5_AMP15 C6_AMP15 CBi_AMP15 Q0_AMP15 Q1_AMP15 Q2_AMP15 Q3_AMP15 R1_AMP15 R2_AMP15 R3_AMP15 R4_AMP15 R5_AMP15 R6_AMP15 R7_AMP15 R8_AMP15 R18_AMP15 R19_AMP15 R20_AMP15 RBi_AMP15 SIPM_AMP15
component class AMP14: C1_AMP14 C2_AMP14 C3_AMP14 C4_AMP14 C5_AMP14 C6_AMP14 CBi_AMP14 Q0_AMP14 Q1_AMP14 Q2_AMP14 Q3_AMP14 R1_AMP14 R2_AMP14 R3_AMP14 R4_AMP14 R5_AMP14 R6_AMP14 R7_AMP14 R8_AMP14 R18_AMP14 R19_AMP14 R20_AMP14 RBi_AMP14 SIPM_AMP14
component class AMP13: C1_AMP13 C2_AMP13 C3_AMP13 C4_AMP13 C5_AMP13 C6_AMP13 CBi_AMP13 Q0_AMP13 Q1_AMP13 Q2_AMP13 Q3_AMP13 R1_AMP13 R2_AMP13 R3_AMP13 R4_AMP13 R5_AMP13 R6_AMP13 R7_AMP13 R8_AMP13 R18_AMP13 R19_AMP13 R20_AMP13 RBi_AMP13 SIPM_AMP13
component class AMP12: C1_AMP12 C2_AMP12 C3_AMP12 C4_AMP12 C5_AMP12 C6_AMP12 CBi_AMP12 Q0_AMP12 Q1_AMP12 Q2_AMP12 Q3_AMP12 R1_AMP12 R2_AMP12 R3_AMP12 R4_AMP12 R5_AMP12 R6_AMP12 R7_AMP12 R8_AMP12 R18_AMP12 R19_AMP12 R20_AMP12 RBi_AMP12 SIPM_AMP12
component class AMP11: C1_AMP11 C2_AMP11 C3_AMP11 C4_AMP11 C5_AMP11 C6_AMP11 CBi_AMP11 Q0_AMP11 Q1_AMP11 Q2_AMP11 Q3_AMP11 R1_AMP11 R2_AMP11 R3_AMP11 R4_AMP11 R5_AMP11 R6_AMP11 R7_AMP11 R8_AMP11 R18_AMP11 R19_AMP11 R20_AMP11 RBi_AMP11 SIPM_AMP11
component class AMP10: C1_AMP10 C2_AMP10 C3_AMP10 C4_AMP10 C5_AMP10 C6_AMP10 CBi_AMP10 Q0_AMP10 Q1_AMP10 Q2_AMP10 Q3_AMP10 R1_AMP10 R2_AMP10 R3_AMP10 R4_AMP10 R5_AMP10 R6_AMP10 R7_AMP10 R8_AMP10 R18_AMP10 R19_AMP10 R20_AMP10 RBi_AMP10 SIPM_AMP10
component class AMP9: C1_AMP9 C2_AMP9 C3_AMP9 C4_AMP9 C5_AMP9 C6_AMP9 CBi_AMP9 Q0_AMP9 Q1_AMP9 Q2_AMP9 Q3_AMP9 R1_AMP9 R2_AMP9 R3_AMP9 R4_AMP9 R5_AMP9 R6_AMP9 R7_AMP9 R8_AMP9 R18_AMP9 R19_AMP9 R20_AMP9 RBi_AMP9 SIPM_AMP9
component class AMP8: C1_AMP8 C2_AMP8 C3_AMP8 C4_AMP8 C5_AMP8 C6_AMP8 CBi_AMP8 Q0_AMP8 Q1_AMP8 Q2_AMP8 Q3_AMP8 R1_AMP8 R2_AMP8 R3_AMP8 R4_AMP8 R5_AMP8 R6_AMP8 R7_AMP8 R8_AMP8 R18_AMP8 R19_AMP8 R20_AMP8 RBi_AMP8 SIPM_AMP8
component class AMP7: C1_AMP7 C2_AMP7 C3_AMP7 C4_AMP7 C5_AMP7 C6_AMP7 CBi_AMP7 Q0_AMP7 Q1_AMP7 Q2_AMP7 Q3_AMP7 R1_AMP7 R2_AMP7 R3_AMP7 R4_AMP7 R5_AMP7 R6_AMP7 R7_AMP7 R8_AMP7 R18_AMP7 R19_AMP7 R20_AMP7 RBi_AMP7 SIPM_AMP7
component class AMP6: C1_AMP6 C2_AMP6 C3_AMP6 C4_AMP6 C5_AMP6 C6_AMP6 CBi_AMP6 Q0_AMP6 Q1_AMP6 Q2_AMP6 Q3_AMP6 R1_AMP6 R2_AMP6 R3_AMP6 R4_AMP6 R5_AMP6 R6_AMP6 R7_AMP6 R8_AMP6 R18_AMP6 R19_AMP6 R20_AMP6 RBi_AMP6 SIPM_AMP6
component class AMP5: C1_AMP5 C2_AMP5 C3_AMP5 C4_AMP5 C5_AMP5 C6_AMP5 CBi_AMP5 Q0_AMP5 Q1_AMP5 Q2_AMP5 Q3_AMP5 R1_AMP5 R2_AMP5 R3_AMP5 R4_AMP5 R5_AMP5 R6_AMP5 R7_AMP5 R8_AMP5 R18_AMP5 R19_AMP5 R20_AMP5 RBi_AMP5 SIPM_AMP5
component class AMP4: C1_AMP4 C2_AMP4 C3_AMP4 C4_AMP4 C5_AMP4 C6_AMP4 CBi_AMP4 Q0_AMP4 Q1_AMP4 Q2_AMP4 Q3_AMP4 R1_AMP4 R2_AMP4 R3_AMP4 R4_AMP4 R5_AMP4 R6_AMP4 R7_AMP4 R8_AMP4 R18_AMP4 R19_AMP4 R20_AMP4 RBi_AMP4 SIPM_AMP4
component class AMP3: C1_AMP3 C2_AMP3 C3_AMP3 C4_AMP3 C5_AMP3 C6_AMP3 CBi_AMP3 Q0_AMP3 Q1_AMP3 Q2_AMP3 Q3_AMP3 R1_AMP3 R2_AMP3 R3_AMP3 R4_AMP3 R5_AMP3 R6_AMP3 R7_AMP3 R8_AMP3 R18_AMP3 R19_AMP3 R20_AMP3 RBi_AMP3 SIPM_AMP3
component class AMP2: C1_AMP2 C2_AMP2 C3_AMP2 C4_AMP2 C5_AMP2 C6_AMP2 CBi_AMP2 Q0_AMP2 Q1_AMP2 Q2_AMP2 Q3_AMP2 R1_AMP2 R2_AMP2 R3_AMP2 R4_AMP2 R5_AMP2 R6_AMP2 R7_AMP2 R8_AMP2 R18_AMP2 R19_AMP2 R20_AMP2 RBi_AMP2 SIPM_AMP2
component class AMP1: C1_AMP1 C2_AMP1 C3_AMP1 C4_AMP1 C5_AMP1 C6_AMP1 CBi_AMP1 Q0_AMP1 Q1_AMP1 Q2_AMP1 Q3_AMP1 R1_AMP1 R2_AMP1 R3_AMP1 R4_AMP1 R5_AMP1 R6_AMP1 R7_AMP1 R8_AMP1 R18_AMP1 R19_AMP1 R20_AMP1 RBi_AMP1 SIPM_AMP1

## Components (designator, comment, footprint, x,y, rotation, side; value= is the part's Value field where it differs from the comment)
C1_AMP1 "Cap" RESC0603L 1334,1317.78 r90 top (schematic designator C1)
C1_AMP2 "Cap" RESC0603L 1517,1317.78 r90 top (schematic designator C1)
C1_AMP3 "Cap" RESC0603L 1700,1317.78 r90 top (schematic designator C1)
C1_AMP4 "Cap" RESC0603L 1884,1317.78 r90 top (schematic designator C1)
C1_AMP5 "Cap" RESC0603L 2067,1317.78 r90 top (schematic designator C1)
C1_AMP6 "Cap" RESC0603L 7030,5577.78 r90 top (schematic designator C1)
C1_AMP7 "Cap" RESC0603L 7492,5572.78 r90 top (schematic designator C1)
C1_AMP8 "Cap" RESC0603L 7989,5596.78 r90 top (schematic designator C1)
C1_AMP9 "Cap" RESC0603L 8440,5589.78 r90 top (schematic designator C1)
C1_AMP10 "Cap" RESC0603L 8869,5572.78 r90 top (schematic designator C1)
C1_AMP11 "Cap" RESC0603L 9281,5548.78 r90 top (schematic designator C1)
C1_AMP12 "Cap" RESC0603L 9845,5570.78 r90 top (schematic designator C1)
C1_AMP13 "Cap" RESC0603L 10232,5548.78 r90 top (schematic designator C1)
C1_AMP14 "Cap" RESC0603L 10598,5548.78 r90 top (schematic designator C1)
C1_AMP15 "Cap" RESC0603L 11066,5505.78 r90 top (schematic designator C1)
C1_AMP16 "Cap" RESC0603L 11488,5537.78 r90 top (schematic designator C1)
C1_AMP17 "Cap" RESC0603L 11876,5549.78 r90 top (schematic designator C1)
C1_AMP18 "Cap" RESC0603L 12332,5347.78 r90 top (schematic designator C1)
C1_AMP19 "Cap" RESC0603L 12724,5543.78 r90 top (schematic designator C1)
C1_AMP20 "Cap" RESC0603L 13214,5396.78 r90 top (schematic designator C1)
C1_AMP21 "Cap" RESC0603L 13764,5502.78 r90 top (schematic designator C1)
C1_AMP22 "Cap" RESC0603L 14469,5444.78 r90 top (schematic designator C1)
C1_AMP23 "Cap" RESC0603L 15278,5502.78 r90 top (schematic designator C1)
C1_AMP24 "Cap" RESC0603L 15736,5544.78 r90 top (schematic designator C1)
C1_AMP25 "Cap" RESC0603L 16235,5523.78 r90 top (schematic designator C1)
C1_AMP26 "Cap" RESC0603L 16692,5492.78 r90 top (schematic designator C1)
C1_AMP27 "Cap" RESC0603L 17222,5503.78 r90 top (schematic designator C1)
C1_AMP28 "Cap" RESC0603L 17753,5503.78 r90 top (schematic designator C1)
C1_AMP29 "Cap" RESC0603L 18170,5544.78 r90 top (schematic designator C1)
C1_AMP30 "Cap" RESC0603L 27288,5676.78 r90 top (schematic designator C1)
C2_AMP1 "Cap" RESC0603L 1264,1317.78 r90 top (schematic designator C2)
C2_AMP2 "Cap" RESC0603L 1447,1317.78 r90 top (schematic designator C2)
C2_AMP3 "Cap" RESC0603L 1630,1317.78 r90 top (schematic designator C2)
C2_AMP4 "Cap" RESC0603L 1814,1317.78 r90 top (schematic designator C2)
C2_AMP5 "Cap" RESC0603L 1997,1317.78 r90 top (schematic designator C2)
C2_AMP6 "Cap" RESC0603L 6960,5577.78 r90 top (schematic designator C2)
C2_AMP7 "Cap" RESC0603L 7422,5572.78 r90 top (schematic designator C2)
C2_AMP8 "Cap" RESC0603L 7919,5596.78 r90 top (schematic designator C2)
C2_AMP9 "Cap" RESC0603L 8370,5589.78 r90 top (schematic designator C2)
C2_AMP10 "Cap" RESC0603L 8799,5572.78 r90 top (schematic designator C2)
C2_AMP11 "Cap" RESC0603L 9211,5548.78 r90 top (schematic designator C2)
C2_AMP12 "Cap" RESC0603L 9775,5570.78 r90 top (schematic designator C2)
C2_AMP13 "Cap" RESC0603L 10162,5548.78 r90 top (schematic designator C2)
C2_AMP14 "Cap" RESC0603L 10528,5548.78 r90 top (schematic designator C2)
C2_AMP15 "Cap" RESC0603L 10996,5505.78 r90 top (schematic designator C2)
C2_AMP16 "Cap" RESC0603L 11418,5537.78 r90 top (schematic designator C2)
C2_AMP17 "Cap" RESC0603L 11806,5549.78 r90 top (schematic designator C2)
C2_AMP18 "Cap" RESC0603L 12262,5347.78 r90 top (schematic designator C2)
C2_AMP19 "Cap" RESC0603L 12654,5543.78 r90 top (schematic designator C2)
C2_AMP20 "Cap" RESC0603L 13144,5396.78 r90 top (schematic designator C2)
C2_AMP21 "Cap" RESC0603L 13694,5502.78 r90 top (schematic designator C2)
C2_AMP22 "Cap" RESC0603L 14399,5444.78 r90 top (schematic designator C2)
C2_AMP23 "Cap" RESC0603L 15208,5502.78 r90 top (schematic designator C2)
C2_AMP24 "Cap" RESC0603L 15666,5544.78 r90 top (schematic designator C2)
C2_AMP25 "Cap" RESC0603L 16165,5523.78 r90 top (schematic designator C2)
C2_AMP26 "Cap" RESC0603L 16622,5492.78 r90 top (schematic designator C2)
C2_AMP27 "Cap" RESC0603L 17152,5503.78 r90 top (schematic designator C2)
C2_AMP28 "Cap" RESC0603L 17683,5503.78 r90 top (schematic designator C2)
C2_AMP29 "Cap" RESC0603L 18100,5544.78 r90 top (schematic designator C2)
C2_AMP30 "Cap" RESC0603L 27218,5676.78 r90 top (schematic designator C2)
C3_AMP1 "Cap" RESC0603L 1395,1610 r90 top (schematic designator C3)
C3_AMP2 "Cap" RESC0603L 1578,1610 r90 top (schematic designator C3)
C3_AMP3 "Cap" RESC0603L 1761,1610 r90 top (schematic designator C3)
C3_AMP4 "Cap" RESC0603L 1945,1610 r90 top (schematic designator C3)
C3_AMP5 "Cap" RESC0603L 2128,1610 r90 top (schematic designator C3)
C3_AMP6 "Cap" RESC0603L 7091,5870 r90 top (schematic designator C3)
C3_AMP7 "Cap" RESC0603L 7553,5865 r90 top (schematic designator C3)
C3_AMP8 "Cap" RESC0603L 8050,5889 r90 top (schematic designator C3)
C3_AMP9 "Cap" RESC0603L 8501,5882 r90 top (schematic designator C3)
C3_AMP10 "Cap" RESC0603L 8930,5865 r90 top (schematic designator C3)
C3_AMP11 "Cap" RESC0603L 9342,5841 r90 top (schematic designator C3)
C3_AMP12 "Cap" RESC0603L 9906,5863 r90 top (schematic designator C3)
C3_AMP13 "Cap" RESC0603L 10293,5841 r90 top (schematic designator C3)
C3_AMP14 "Cap" RESC0603L 10659,5841 r90 top (schematic designator C3)
C3_AMP15 "Cap" RESC0603L 11127,5798 r90 top (schematic designator C3)
C3_AMP16 "Cap" RESC0603L 11549,5830 r90 top (schematic designator C3)
C3_AMP17 "Cap" RESC0603L 11937,5842 r90 top (schematic designator C3)
C3_AMP18 "Cap" RESC0603L 12393,5640 r90 top (schematic designator C3)
C3_AMP19 "Cap" RESC0603L 12785,5836 r90 top (schematic designator C3)
C3_AMP20 "Cap" RESC0603L 13275,5689 r90 top (schematic designator C3)
C3_AMP21 "Cap" RESC0603L 13825,5795 r90 top (schematic designator C3)
C3_AMP22 "Cap" RESC0603L 14530,5737 r90 top (schematic designator C3)
C3_AMP23 "Cap" RESC0603L 15339,5795 r90 top (schematic designator C3)
C3_AMP24 "Cap" RESC0603L 15797,5837 r90 top (schematic designator C3)
C3_AMP25 "Cap" RESC0603L 16296,5816 r90 top (schematic designator C3)
C3_AMP26 "Cap" RESC0603L 16753,5785 r90 top (schematic designator C3)
C3_AMP27 "Cap" RESC0603L 17283,5796 r90 top (schematic designator C3)
C3_AMP28 "Cap" RESC0603L 17814,5796 r90 top (schematic designator C3)
C3_AMP29 "Cap" RESC0603L 18231,5837 r90 top (schematic designator C3)
C3_AMP30 "Cap" RESC0603L 27349,5969 r90 top (schematic designator C3)
C4_AMP1 "Cap" RESC0603L 1330,1610 r90 top (schematic designator C4)
C4_AMP2 "Cap" RESC0603L 1513,1610 r90 top (schematic designator C4)
C4_AMP3 "Cap" RESC0603L 1696,1610 r90 top (schematic designator C4)
C4_AMP4 "Cap" RESC0603L 1880,1610 r90 top (schematic designator C4)
C4_AMP5 "Cap" RESC0603L 2063,1610 r90 top (schematic designator C4)
C4_AMP6 "Cap" RESC0603L 7026,5870 r90 top (schematic designator C4)
C4_AMP7 "Cap" RESC0603L 7488,5865 r90 top (schematic designator C4)
C4_AMP8 "Cap" RESC0603L 7985,5889 r90 top (schematic designator C4)
C4_AMP9 "Cap" RESC0603L 8436,5882 r90 top (schematic designator C4)
C4_AMP10 "Cap" RESC0603L 8865,5865 r90 top (schematic designator C4)
C4_AMP11 "Cap" RESC0603L 9277,5841 r90 top (schematic designator C4)
C4_AMP12 "Cap" RESC0603L 9841,5863 r90 top (schematic designator C4)
C4_AMP13 "Cap" RESC0603L 10228,5841 r90 top (schematic designator C4)
C4_AMP14 "Cap" RESC0603L 10594,5841 r90 top (schematic designator C4)
C4_AMP15 "Cap" RESC0603L 11062,5798 r90 top (schematic designator C4)
C4_AMP16 "Cap" RESC0603L 11484,5830 r90 top (schematic designator C4)
C4_AMP17 "Cap" RESC0603L 11872,5842 r90 top (schematic designator C4)
C4_AMP18 "Cap" RESC0603L 12328,5640 r90 top (schematic designator C4)
C4_AMP19 "Cap" RESC0603L 12720,5836 r90 top (schematic designator C4)
C4_AMP20 "Cap" RESC0603L 13210,5689 r90 top (schematic designator C4)
C4_AMP21 "Cap" RESC0603L 13760,5795 r90 top (schematic designator C4)
C4_AMP22 "Cap" RESC0603L 14465,5737 r90 top (schematic designator C4)
C4_AMP23 "Cap" RESC0603L 15274,5795 r90 top (schematic designator C4)
C4_AMP24 "Cap" RESC0603L 15732,5837 r90 top (schematic designator C4)
C4_AMP25 "Cap" RESC0603L 16231,5816 r90 top (schematic designator C4)
C4_AMP26 "Cap" RESC0603L 16688,5785 r90 top (schematic designator C4)
C4_AMP27 "Cap" RESC0603L 17218,5796 r90 top (schematic designator C4)
C4_AMP28 "Cap" RESC0603L 17749,5796 r90 top (schematic designator C4)
C4_AMP29 "Cap" RESC0603L 18166,5837 r90 top (schematic designator C4)
C4_AMP30 "Cap" RESC0603L 27284,5969 r90 top (schematic designator C4)
C5_AMP1 "Cap" RESC0603L 1369,1869 r90 top (schematic designator C5)
C5_AMP2 "Cap" RESC0603L 1552,1869 r90 top (schematic designator C5)
C5_AMP3 "Cap" RESC0603L 1735,1869 r90 top (schematic designator C5)
C5_AMP4 "Cap" RESC0603L 1919,1869 r90 top (schematic designator C5)
C5_AMP5 "Cap" RESC0603L 2102,1869 r90 top (schematic designator C5)
C5_AMP6 "Cap" RESC0603L 7050,6058 r90 top (schematic designator C5)
C5_AMP7 "Cap" RESC0603L 7527,6124 r90 top (schematic designator C5)
C5_AMP8 "Cap" RESC0603L 8024,6148 r90 top (schematic designator C5)
C5_AMP9 "Cap" RESC0603L 8475,6141 r90 top (schematic designator C5)
C5_AMP10 "Cap" RESC0603L 8904,6124 r90 top (schematic designator C5)
C5_AMP11 "Cap" RESC0603L 9316,6100 r90 top (schematic designator C5)
C5_AMP12 "Cap" RESC0603L 9880,6122 r90 top (schematic designator C5)
C5_AMP13 "Cap" RESC0603L 10267,6100 r90 top (schematic designator C5)
C5_AMP14 "Cap" RESC0603L 10633,6100 r90 top (schematic designator C5)
C5_AMP15 "Cap" RESC0603L 11101,6057 r90 top (schematic designator C5)
C5_AMP16 "Cap" RESC0603L 11523,6089 r90 top (schematic designator C5)
C5_AMP17 "Cap" RESC0603L 11911,6101 r90 top (schematic designator C5)
C5_AMP18 "Cap" RESC0603L 12367,5899 r90 top (schematic designator C5)
C5_AMP19 "Cap" RESC0603L 12759,6095 r90 top (schematic designator C5)
C5_AMP20 "Cap" RESC0603L 13249,5948 r90 top (schematic designator C5)
C5_AMP21 "Cap" RESC0603L 13799,6054 r90 top (schematic designator C5)
C5_AMP22 "Cap" RESC0603L 14504,5996 r90 top (schematic designator C5)
C5_AMP23 "Cap" RESC0603L 15313,6054 r90 top (schematic designator C5)
C5_AMP24 "Cap" RESC0603L 15771,6096 r90 top (schematic designator C5)
C5_AMP25 "Cap" RESC0603L 16270,6075 r90 top (schematic designator C5)
C5_AMP26 "Cap" RESC0603L 16727,6044 r90 top (schematic designator C5)
C5_AMP27 "Cap" RESC0603L 17257,6055 r90 top (schematic designator C5)
C5_AMP28 "Cap" RESC0603L 17788,6055 r90 top (schematic designator C5)
C5_AMP29 "Cap" RESC0603L 18205,6096 r90 top (schematic designator C5)
C5_AMP30 "Cap" RESC0603L 27323,6228 r90 top (schematic designator C5)
C5_SUMMER1 "Cap" RESC0603L 1559,2677 r90 top (schematic designator C5)
C5_SUMMER2 "Cap" RESC0603L 15115,9350 r90 top (schematic designator C5)
C5_SUMMER3 "Cap" RESC0603L 15115,13090 r90 top (schematic designator C5)
C5_SUMMER4 "Cap" RESC0603L 15115,17010 r90 top (schematic designator C5)
C5_SUMMER5 "Cap" RESC0603L 15115,20960 r90 top (schematic designator C5)
C5_SUMMER6 "Cap" RESC0603L 15076,23238 r90 top (schematic designator C5)
C6_AMP1 "Cap" RESC0603L 1399,1869 r270 top (schematic designator C6)
C6_AMP2 "Cap" RESC0603L 1582,1869 r270 top (schematic designator C6)
C6_AMP3 "Cap" RESC0603L 1765,1869 r270 top (schematic designator C6)
C6_AMP4 "Cap" RESC0603L 1949,1869 r270 top (schematic designator C6)
C6_AMP5 "Cap" RESC0603L 2132,1869 r270 top (schematic designator C6)
C6_AMP6 "Cap" RESC0603L 7095,6132 r270 top (schematic designator C6)
C6_AMP7 "Cap" RESC0603L 7557,6124 r270 top (schematic designator C6)
C6_AMP8 "Cap" RESC0603L 8054,6148 r270 top (schematic designator C6)
C6_AMP9 "Cap" RESC0603L 8505,6141 r270 top (schematic designator C6)
C6_AMP10 "Cap" RESC0603L 8934,6124 r270 top (schematic designator C6)
C6_AMP11 "Cap" RESC0603L 9346,6100 r270 top (schematic designator C6)
C6_AMP12 "Cap" RESC0603L 9910,6122 r270 top (schematic designator C6)
C6_AMP13 "Cap" RESC0603L 10297,6100 r270 top (schematic designator C6)
C6_AMP14 "Cap" RESC0603L 10663,6100 r270 top (schematic designator C6)
C6_AMP15 "Cap" RESC0603L 11131,6057 r270 top (schematic designator C6)
C6_AMP16 "Cap" RESC0603L 11553,6089 r270 top (schematic designator C6)
C6_AMP17 "Cap" RESC0603L 11941,6101 r270 top (schematic designator C6)
C6_AMP18 "Cap" RESC0603L 12397,5899 r270 top (schematic designator C6)
C6_AMP19 "Cap" RESC0603L 12789,6095 r270 top (schematic designator C6)
C6_AMP20 "Cap" RESC0603L 13279,5948 r270 top (schematic designator C6)
C6_AMP21 "Cap" RESC0603L 13829,6054 r270 top (schematic designator C6)
C6_AMP22 "Cap" RESC0603L 14534,5996 r270 top (schematic designator C6)
C6_AMP23 "Cap" RESC0603L 15343,6054 r270 top (schematic designator C6)
C6_AMP24 "Cap" RESC0603L 15801,6096 r270 top (schematic designator C6)
C6_AMP25 "Cap" RESC0603L 16300,6075 r270 top (schematic designator C6)
C6_AMP26 "Cap" RESC0603L 16757,6044 r270 top (schematic designator C6)
C6_AMP27 "Cap" RESC0603L 17287,6055 r270 top (schematic designator C6)
C6_AMP28 "Cap" RESC0603L 17818,6055 r270 top (schematic designator C6)
C6_AMP29 "Cap" RESC0603L 18235,6096 r270 top (schematic designator C6)
C6_AMP30 "Cap" RESC0603L 27353,6228 r270 top (schematic designator C6)
C7_SUMMER1 "Cap" RESC0603L 1560,2440 r90 top (schematic designator C7)
C7_SUMMER2 "Cap" RESC0603L 10465,9350 r90 top (schematic designator C7)
C7_SUMMER3 "Cap" RESC0603L 10465,13090 r90 top (schematic designator C7)
C7_SUMMER4 "Cap" RESC0603L 10465,17010 r90 top (schematic designator C7)
C7_SUMMER5 "Cap" RESC0603L 10465,20960 r90 top (schematic designator C7)
C7_SUMMER6 "Cap" RESC0603L 10426,23238 r90 top (schematic designator C7)
C8_SUMMER1 "Cap" RESC0603L 1970,2545 r90 top (schematic designator C8)
C8_SUMMER2 "Cap" RESC0603L 15765,9350 r90 top (schematic designator C8)
C8_SUMMER3 "Cap" RESC0603L 15765,13090 r90 top (schematic designator C8)
C8_SUMMER4 "Cap" RESC0603L 15765,17010 r90 top (schematic designator C8)
C8_SUMMER5 "Cap" RESC0603L 15765,20960 r90 top (schematic designator C8)
C8_SUMMER6 "Cap" RESC0603L 15726,23238 r90 top (schematic designator C8)
C9_SUMMER1 "Cap" RESC0603L 1285,2520 r270 top (schematic designator C9)
C9_SUMMER2 "Cap" RESC0603L 21095,9350 r90 top (schematic designator C9)
C9_SUMMER3 "Cap" RESC0603L 21095,13090 r90 top (schematic designator C9)
C9_SUMMER4 "Cap" RESC0603L 21095,17010 r90 top (schematic designator C9)
C9_SUMMER5 "Cap" RESC0603L 21095,20960 r90 top (schematic designator C9)
C9_SUMMER6 "Cap" RESC0603L 21056,23238 r90 top (schematic designator C9)
CBi_AMP1 "Cap" RESC0603L 1259,1610 r90 top (schematic designator CBi)
CBi_AMP2 "Cap" RESC0603L 1442,1610 r90 top (schematic designator CBi)
CBi_AMP3 "Cap" RESC0603L 1625,1610 r90 top (schematic designator CBi)
CBi_AMP4 "Cap" RESC0603L 1809,1610 r90 top (schematic designator CBi)
CBi_AMP5 "Cap" RESC0603L 1992,1610 r90 top (schematic designator CBi)
CBi_AMP6 "Cap" RESC0603L 6955,5870 r90 top (schematic designator CBi)
CBi_AMP7 "Cap" RESC0603L 7417,5865 r90 top (schematic designator CBi)
CBi_AMP8 "Cap" RESC0603L 7914,5889 r90 top (schematic designator CBi)
CBi_AMP9 "Cap" RESC0603L 8365,5882 r90 top (schematic designator CBi)
CBi_AMP10 "Cap" RESC0603L 8794,5865 r90 top (schematic designator CBi)
CBi_AMP11 "Cap" RESC0603L 9206,5841 r90 top (schematic designator CBi)
CBi_AMP12 "Cap" RESC0603L 9770,5863 r90 top (schematic designator CBi)
CBi_AMP13 "Cap" RESC0603L 10157,5841 r90 top (schematic designator CBi)
CBi_AMP14 "Cap" RESC0603L 10523,5841 r90 top (schematic designator CBi)
CBi_AMP15 "Cap" RESC0603L 10991,5798 r90 top (schematic designator CBi)
CBi_AMP16 "Cap" RESC0603L 11413,5830 r90 top (schematic designator CBi)
CBi_AMP17 "Cap" RESC0603L 11801,5842 r90 top (schematic designator CBi)
CBi_AMP18 "Cap" RESC0603L 12257,5640 r90 top (schematic designator CBi)
CBi_AMP19 "Cap" RESC0603L 12649,5836 r90 top (schematic designator CBi)
CBi_AMP20 "Cap" RESC0603L 13139,5689 r90 top (schematic designator CBi)
CBi_AMP21 "Cap" RESC0603L 13689,5795 r90 top (schematic designator CBi)
CBi_AMP22 "Cap" RESC0603L 14394,5737 r90 top (schematic designator CBi)
CBi_AMP23 "Cap" RESC0603L 15203,5795 r90 top (schematic designator CBi)
CBi_AMP24 "Cap" RESC0603L 15661,5837 r90 top (schematic designator CBi)
CBi_AMP25 "Cap" RESC0603L 16160,5816 r90 top (schematic designator CBi)
CBi_AMP26 "Cap" RESC0603L 16617,5785 r90 top (schematic designator CBi)
CBi_AMP27 "Cap" RESC0603L 17147,5796 r90 top (schematic designator CBi)
CBi_AMP28 "Cap" RESC0603L 17678,5796 r90 top (schematic designator CBi)
CBi_AMP29 "Cap" RESC0603L 18095,5837 r90 top (schematic designator CBi)
CBi_AMP30 "Cap" RESC0603L 27213,5969 r90 top (schematic designator CBi)
CBi_SUMMER1 "Cap" RESC0603L 1550,2555 r180 top (schematic designator CBi)
CBi_SUMMER2 "Cap" RESC0603L 13115,9350 r90 top (schematic designator CBi)
CBi_SUMMER3 "Cap" RESC0603L 13115,13090 r90 top (schematic designator CBi)
CBi_SUMMER4 "Cap" RESC0603L 13115,17010 r90 top (schematic designator CBi)
CBi_SUMMER5 "Cap" RESC0603L 13115,20960 r90 top (schematic designator CBi)
CBi_SUMMER6 "Cap" RESC0603L 13076,23238 r90 top (schematic designator CBi)
CG_SUMMER1 "Cap" RESC0603L 2055,2720 r0 top (schematic designator CG)
CG_SUMMER2 "Cap" RESC0603L 22445,9350 r90 top (schematic designator CG)
CG_SUMMER3 "Cap" RESC0603L 22445,13090 r90 top (schematic designator CG)
CG_SUMMER4 "Cap" RESC0603L 22445,17010 r90 top (schematic designator CG)
CG_SUMMER5 "Cap" RESC0603L 22445,20960 r90 top (schematic designator CG)
CG_SUMMER6 "Cap" RESC0603L 22406,23238 r90 top (schematic designator CG)
D1 "D Zener 5.1V" DIODE-0.7 2487,3767 r180 top
M1_SUMMER1 "MOSFET-N" SOT-143 1930,2710 r180 top (schematic designator M1)
M1_SUMMER2 "MOSFET-N" SOT-143 19895,9245 r90 top (schematic designator M1)
M1_SUMMER3 "MOSFET-N" SOT-143 19895,12985 r90 top (schematic designator M1)
M1_SUMMER4 "MOSFET-N" SOT-143 19895,16905 r90 top (schematic designator M1)
M1_SUMMER5 "MOSFET-N" SOT-143 19895,20855 r90 top (schematic designator M1)
M1_SUMMER6 "MOSFET-N" SOT-143 19856,23133 r90 top (schematic designator M1)
P1 "DIN41612 96 pin, Backplane" EURO2.54-2V96 3972,3312 r180 top
Q0_AMP1 "BFR92P" SOT23_N 1324,1501.56 r0 top (schematic designator Q0)
Q0_AMP2 "BFR92P" SOT23_N 1507,1501.56 r0 top (schematic designator Q0)
Q0_AMP3 "BFR92P" SOT23_N 1690,1501.56 r0 top (schematic designator Q0)
Q0_AMP4 "BFR92P" SOT23_N 1874,1501.56 r0 top (schematic designator Q0)
Q0_AMP5 "BFR92P" SOT23_N 2057,1501.56 r0 top (schematic designator Q0)
Q0_AMP6 "BFR92P" SOT23_N 7020,5761.56 r0 top (schematic designator Q0)
Q0_AMP7 "BFR92P" SOT23_N 7482,5756.56 r0 top (schematic designator Q0)
Q0_AMP8 "BFR92P" SOT23_N 7979,5780.56 r0 top (schematic designator Q0)
Q0_AMP9 "BFR92P" SOT23_N 8430,5773.56 r0 top (schematic designator Q0)
Q0_AMP10 "BFR92P" SOT23_N 8859,5756.56 r0 top (schematic designator Q0)
Q0_AMP11 "BFR92P" SOT23_N 9271,5732.56 r0 top (schematic designator Q0)
Q0_AMP12 "BFR92P" SOT23_N 9835,5754.56 r0 top (schematic designator Q0)
Q0_AMP13 "BFR92P" SOT23_N 10222,5732.56 r0 top (schematic designator Q0)
Q0_AMP14 "BFR92P" SOT23_N 10588,5732.56 r0 top (schematic designator Q0)
Q0_AMP15 "BFR92P" SOT23_N 11056,5689.56 r0 top (schematic designator Q0)
Q0_AMP16 "BFR92P" SOT23_N 11478,5721.56 r0 top (schematic designator Q0)
Q0_AMP17 "BFR92P" SOT23_N 11866,5733.56 r0 top (schematic designator Q0)
Q0_AMP18 "BFR92P" SOT23_N 12322,5531.56 r0 top (schematic designator Q0)
Q0_AMP19 "BFR92P" SOT23_N 12714,5727.56 r0 top (schematic designator Q0)
Q0_AMP20 "BFR92P" SOT23_N 13204,5580.56 r0 top (schematic designator Q0)
Q0_AMP21 "BFR92P" SOT23_N 13754,5686.56 r0 top (schematic designator Q0)
Q0_AMP22 "BFR92P" SOT23_N 14459,5628.56 r0 top (schematic designator Q0)
Q0_AMP23 "BFR92P" SOT23_N 15268,5686.56 r0 top (schematic designator Q0)
Q0_AMP24 "BFR92P" SOT23_N 15726,5728.56 r0 top (schematic designator Q0)
Q0_AMP25 "BFR92P" SOT23_N 16225,5707.56 r0 top (schematic designator Q0)
Q0_AMP26 "BFR92P" SOT23_N 16682,5676.56 r0 top (schematic designator Q0)
Q0_AMP27 "BFR92P" SOT23_N 17212,5687.56 r0 top (schematic designator Q0)
Q0_AMP28 "BFR92P" SOT23_N 17743,5687.56 r0 top (schematic designator Q0)
Q0_AMP29 "BFR92P" SOT23_N 18160,5728.56 r0 top (schematic designator Q0)
Q0_AMP30 "BFR92P" SOT23_N 27278,5860.56 r0 top (schematic designator Q0)
Q1_AMP1 "BPR92P" SOT23_N 1324,2229 r180 top (schematic designator Q1)
Q1_AMP2 "BPR92P" SOT23_N 1507,2229 r180 top (schematic designator Q1)
Q1_AMP3 "BPR92P" SOT23_N 1690,2229 r180 top (schematic designator Q1)
Q1_AMP4 "BPR92P" SOT23_N 1874,2229 r180 top (schematic designator Q1)
Q1_AMP5 "BPR92P" SOT23_N 2057,2229 r180 top (schematic designator Q1)
Q1_AMP6 "BPR92P" SOT23_N 7020,6489 r180 top (schematic designator Q1)
Q1_AMP7 "BPR92P" SOT23_N 7482,6484 r180 top (schematic designator Q1)
Q1_AMP8 "BPR92P" SOT23_N 7979,6508 r180 top (schematic designator Q1)
Q1_AMP9 "BPR92P" SOT23_N 8430,6501 r180 top (schematic designator Q1)
Q1_AMP10 "BPR92P" SOT23_N 8859,6484 r180 top (schematic designator Q1)
Q1_AMP11 "BPR92P" SOT23_N 9271,6460 r180 top (schematic designator Q1)
Q1_AMP12 "BPR92P" SOT23_N 9835,6482 r180 top (schematic designator Q1)
Q1_AMP13 "BPR92P" SOT23_N 10222,6460 r180 top (schematic designator Q1)
Q1_AMP14 "BPR92P" SOT23_N 10588,6460 r180 top (schematic designator Q1)
Q1_AMP15 "BPR92P" SOT23_N 11056,6417 r180 top (schematic designator Q1)
Q1_AMP16 "BPR92P" SOT23_N 11478,6449 r180 top (schematic designator Q1)
Q1_AMP17 "BPR92P" SOT23_N 11866,6461 r180 top (schematic designator Q1)
Q1_AMP18 "BPR92P" SOT23_N 12322,6259 r180 top (schematic designator Q1)
Q1_AMP19 "BPR92P" SOT23_N 12714,6455 r180 top (schematic designator Q1)
Q1_AMP20 "BPR92P" SOT23_N 13204,6308 r180 top (schematic designator Q1)
Q1_AMP21 "BPR92P" SOT23_N 13754,6414 r180 top (schematic designator Q1)
Q1_AMP22 "BPR92P" SOT23_N 14459,6356 r180 top (schematic designator Q1)
Q1_AMP23 "BPR92P" SOT23_N 15268,6414 r180 top (schematic designator Q1)
Q1_AMP24 "BPR92P" SOT23_N 15726,6456 r180 top (schematic designator Q1)
Q1_AMP25 "BPR92P" SOT23_N 16225,6435 r180 top (schematic designator Q1)
Q1_AMP26 "BPR92P" SOT23_N 16682,6404 r180 top (schematic designator Q1)
Q1_AMP27 "BPR92P" SOT23_N 17212,6415 r180 top (schematic designator Q1)
Q1_AMP28 "BPR92P" SOT23_N 17743,6415 r180 top (schematic designator Q1)
Q1_AMP29 "BPR92P" SOT23_N 18160,6456 r180 top (schematic designator Q1)
Q1_AMP30 "BPR92P" SOT23_N 27278,6588 r180 top (schematic designator Q1)
Q2_AMP1 "BFT92W" SOT323_L 1301,1874 r90 top (schematic designator Q2)
Q2_AMP2 "BFT92W" SOT323_L 1484,1874 r90 top (schematic designator Q2)
Q2_AMP3 "BFT92W" SOT323_L 1667,1874 r90 top (schematic designator Q2)
Q2_AMP4 "BFT92W" SOT323_L 1851,1874 r90 top (schematic designator Q2)
Q2_AMP5 "BFT92W" SOT323_L 2034,1874 r90 top (schematic designator Q2)
Q2_AMP6 "BFT92W" SOT323_L 6988,6135 r90 top (schematic designator Q2)
Q2_AMP7 "BFT92W" SOT323_L 7459,6129 r90 top (schematic designator Q2)
Q2_AMP8 "BFT92W" SOT323_L 7956,6153 r90 top (schematic designator Q2)
Q2_AMP9 "BFT92W" SOT323_L 8407,6146 r90 top (schematic designator Q2)
Q2_AMP10 "BFT92W" SOT323_L 8836,6129 r90 top (schematic designator Q2)
Q2_AMP11 "BFT92W" SOT323_L 9248,6105 r90 top (schematic designator Q2)
Q2_AMP12 "BFT92W" SOT323_L 9812,6127 r90 top (schematic designator Q2)
Q2_AMP13 "BFT92W" SOT323_L 10199,6105 r90 top (schematic designator Q2)
Q2_AMP14 "BFT92W" SOT323_L 10565,6105 r90 top (schematic designator Q2)
Q2_AMP15 "BFT92W" SOT323_L 11033,6062 r90 top (schematic designator Q2)
Q2_AMP16 "BFT92W" SOT323_L 11455,6094 r90 top (schematic designator Q2)
Q2_AMP17 "BFT92W" SOT323_L 11843,6106 r90 top (schematic designator Q2)
Q2_AMP18 "BFT92W" SOT323_L 12299,5904 r90 top (schematic designator Q2)
Q2_AMP19 "BFT92W" SOT323_L 12691,6100 r90 top (schematic designator Q2)
Q2_AMP20 "BFT92W" SOT323_L 13181,5953 r90 top (schematic designator Q2)
Q2_AMP21 "BFT92W" SOT323_L 13731,6059 r90 top (schematic designator Q2)
Q2_AMP22 "BFT92W" SOT323_L 14436,6001 r90 top (schematic designator Q2)
Q2_AMP23 "BFT92W" SOT323_L 15245,6059 r90 top (schematic designator Q2)
Q2_AMP24 "BFT92W" SOT323_L 15703,6101 r90 top (schematic designator Q2)
Q2_AMP25 "BFT92W" SOT323_L 16202,6080 r90 top (schematic designator Q2)
Q2_AMP26 "BFT92W" SOT323_L 16659,6049 r90 top (schematic designator Q2)
Q2_AMP27 "BFT92W" SOT323_L 17189,6060 r90 top (schematic designator Q2)
Q2_AMP28 "BFT92W" SOT323_L 17720,6060 r90 top (schematic designator Q2)
Q2_AMP29 "BFT92W" SOT323_L 18137,6101 r90 top (schematic designator Q2)
Q2_AMP30 "BFT92W" SOT323_L 27255,6233 r90 top (schematic designator Q2)
Q3_AMP1 "BFT92W" SOT323_L 1311,2048 r0 top (schematic designator Q3)
Q3_AMP2 "BFT92W" SOT323_L 1494,2048 r0 top (schematic designator Q3)
Q3_AMP3 "BFT92W" SOT323_L 1677,2048 r0 top (schematic designator Q3)
Q3_AMP4 "BFT92W" SOT323_L 1861,2048 r0 top (schematic designator Q3)
Q3_AMP5 "BFT92W" SOT323_L 2044,2048 r0 top (schematic designator Q3)
Q3_AMP6 "BFT92W" SOT323_L 7010,6280 r90 top (schematic designator Q3)
Q3_AMP7 "BFT92W" SOT323_L 7469,6303 r0 top (schematic designator Q3)
Q3_AMP8 "BFT92W" SOT323_L 7966,6327 r0 top (schematic designator Q3)
Q3_AMP9 "BFT92W" SOT323_L 8417,6320 r0 top (schematic designator Q3)
Q3_AMP10 "BFT92W" SOT323_L 8846,6303 r0 top (schematic designator Q3)
Q3_AMP11 "BFT92W" SOT323_L 9258,6279 r0 top (schematic designator Q3)
Q3_AMP12 "BFT92W" SOT323_L 9822,6301 r0 top (schematic designator Q3)
Q3_AMP13 "BFT92W" SOT323_L 10209,6279 r0 top (schematic designator Q3)
Q3_AMP14 "BFT92W" SOT323_L 10575,6279 r0 top (schematic designator Q3)
Q3_AMP15 "BFT92W" SOT323_L 11043,6236 r0 top (schematic designator Q3)
Q3_AMP16 "BFT92W" SOT323_L 11465,6268 r0 top (schematic designator Q3)
Q3_AMP17 "BFT92W" SOT323_L 11853,6280 r0 top (schematic designator Q3)
Q3_AMP18 "BFT92W" SOT323_L 12309,6078 r0 top (schematic designator Q3)
Q3_AMP19 "BFT92W" SOT323_L 12701,6274 r0 top (schematic designator Q3)
Q3_AMP20 "BFT92W" SOT323_L 13191,6127 r0 top (schematic designator Q3)
Q3_AMP21 "BFT92W" SOT323_L 13741,6233 r0 top (schematic designator Q3)
Q3_AMP22 "BFT92W" SOT323_L 14446,6175 r0 top (schematic designator Q3)
Q3_AMP23 "BFT92W" SOT323_L 15255,6233 r0 top (schematic designator Q3)
Q3_AMP24 "BFT92W" SOT323_L 15713,6275 r0 top (schematic designator Q3)
Q3_AMP25 "BFT92W" SOT323_L 16212,6254 r0 top (schematic designator Q3)
Q3_AMP26 "BFT92W" SOT323_L 16669,6223 r0 top (schematic designator Q3)
Q3_AMP27 "BFT92W" SOT323_L 17199,6234 r0 top (schematic designator Q3)
Q3_AMP28 "BFT92W" SOT323_L 17730,6234 r0 top (schematic designator Q3)
Q3_AMP29 "BFT92W" SOT323_L 18147,6275 r0 top (schematic designator Q3)
Q3_AMP30 "BFT92W" SOT323_L 27265,6407 r0 top (schematic designator Q3)
Q4_SUMMER1 "BFR92P" SOT23_N 1660,2520 r0 top (schematic designator Q4)
Q4_SUMMER2 "BFR92P" SOT23_N 11185,9300 r90 top (schematic designator Q4)
Q4_SUMMER3 "BFR92P" SOT23_N 11185,13040 r90 top (schematic designator Q4)
Q4_SUMMER4 "BFR92P" SOT23_N 11185,16960 r90 top (schematic designator Q4)
Q4_SUMMER5 "BFR92P" SOT23_N 11185,20910 r90 top (schematic designator Q4)
Q4_SUMMER6 "BFR92P" SOT23_N 11146,23188 r90 top (schematic designator Q4)
Q5_SUMMER1 "BFR92P" SOT23_N 1654,2667 r180 top (schematic designator Q5)
Q5_SUMMER2 "BFR92P" SOT23_N 11835,9300 r90 top (schematic designator Q5)
Q5_SUMMER3 "BFR92P" SOT23_N 11835,13040 r90 top (schematic designator Q5)
Q5_SUMMER4 "BFR92P" SOT23_N 11835,16960 r90 top (schematic designator Q5)
Q5_SUMMER5 "BFR92P" SOT23_N 11835,20910 r90 top (schematic designator Q5)
Q5_SUMMER6 "BFR92P" SOT23_N 11796,23188 r90 top (schematic designator Q5)
Q6_SUMMER1 "BFT92W" SOT323_L 1445,2690 r180 top (schematic designator Q6)
Q6_SUMMER2 "BFT92W" SOT323_L 14520,9320 r90 top (schematic designator Q6)
Q6_SUMMER3 "BFT92W" SOT323_L 14520,13060 r90 top (schematic designator Q6)
Q6_SUMMER4 "BFT92W" SOT323_L 14520,16980 r90 top (schematic designator Q6)
Q6_SUMMER5 "BFT92W" SOT323_L 14520,20930 r90 top (schematic designator Q6)
Q6_SUMMER6 "BFT92W" SOT323_L 14481,23208 r90 top (schematic designator Q6)
Q7_SUMMER1 "BFT92W" SOT323_L 1375,2585 r180 top (schematic designator Q7)
Q7_SUMMER2 "BFT92W" SOT323_L 16470,9320 r90 top (schematic designator Q7)
Q7_SUMMER3 "BFT92W" SOT323_L 16470,13060 r90 top (schematic designator Q7)
Q7_SUMMER4 "BFT92W" SOT323_L 16470,16980 r90 top (schematic designator Q7)
Q7_SUMMER5 "BFT92W" SOT323_L 16470,20930 r90 top (schematic designator Q7)
Q7_SUMMER6 "BFT92W" SOT323_L 16431,23208 r90 top (schematic designator Q7)
Q8_SUMMER1 "BFR92P" SOT23_N 1865,2530 r180 top (schematic designator Q8)
Q8_SUMMER2 "BFR92P" SOT23_N 13885,9300 r90 top (schematic designator Q8)
Q8_SUMMER3 "BFR92P" SOT23_N 13885,13040 r90 top (schematic designator Q8)
Q8_SUMMER4 "BFR92P" SOT23_N 13885,16960 r90 top (schematic designator Q8)
Q8_SUMMER5 "BFR92P" SOT23_N 13885,20910 r90 top (schematic designator Q8)
Q8_SUMMER6 "BFR92P" SOT23_N 13846,23188 r90 top (schematic designator Q8)
R1_AMP1 "Res2" RESC0603L 1294,1317.78 r90 top (schematic designator R1)
R1_AMP2 "Res2" RESC0603L 1477,1317.78 r90 top (schematic designator R1)
R1_AMP3 "Res2" RESC0603L 1660,1317.78 r90 top (schematic designator R1)
R1_AMP4 "Res2" RESC0603L 1844,1317.78 r90 top (schematic designator R1)
R1_AMP5 "Res2" RESC0603L 2027,1317.78 r90 top (schematic designator R1)
R1_AMP6 "Res2" RESC0603L 6990,5577.78 r90 top (schematic designator R1)
R1_AMP7 "Res2" RESC0603L 7452,5572.78 r90 top (schematic designator R1)
R1_AMP8 "Res2" RESC0603L 7949,5596.78 r90 top (schematic designator R1)
R1_AMP9 "Res2" RESC0603L 8400,5589.78 r90 top (schematic designator R1)
R1_AMP10 "Res2" RESC0603L 8829,5572.78 r90 top (schematic designator R1)
R1_AMP11 "Res2" RESC0603L 9241,5548.78 r90 top (schematic designator R1)
R1_AMP12 "Res2" RESC0603L 9805,5570.78 r90 top (schematic designator R1)
R1_AMP13 "Res2" RESC0603L 10192,5548.78 r90 top (schematic designator R1)
R1_AMP14 "Res2" RESC0603L 10558,5548.78 r90 top (schematic designator R1)
R1_AMP15 "Res2" RESC0603L 11026,5505.78 r90 top (schematic designator R1)
R1_AMP16 "Res2" RESC0603L 11448,5537.78 r90 top (schematic designator R1)
R1_AMP17 "Res2" RESC0603L 11836,5549.78 r90 top (schematic designator R1)
R1_AMP18 "Res2" RESC0603L 12292,5347.78 r90 top (schematic designator R1)
R1_AMP19 "Res2" RESC0603L 12684,5543.78 r90 top (schematic designator R1)
R1_AMP20 "Res2" RESC0603L 13174,5396.78 r90 top (schematic designator R1)
R1_AMP21 "Res2" RESC0603L 13724,5502.78 r90 top (schematic designator R1)
R1_AMP22 "Res2" RESC0603L 14429,5444.78 r90 top (schematic designator R1)
R1_AMP23 "Res2" RESC0603L 15238,5502.78 r90 top (schematic designator R1)
R1_AMP24 "Res2" RESC0603L 15696,5544.78 r90 top (schematic designator R1)
R1_AMP25 "Res2" RESC0603L 16195,5523.78 r90 top (schematic designator R1)
R1_AMP26 "Res2" RESC0603L 16652,5492.78 r90 top (schematic designator R1)
R1_AMP27 "Res2" RESC0603L 17182,5503.78 r90 top (schematic designator R1)
R1_AMP28 "Res2" RESC0603L 17713,5503.78 r90 top (schematic designator R1)
R1_AMP29 "Res2" RESC0603L 18130,5544.78 r90 top (schematic designator R1)
R1_AMP30 "Res2" RESC0603L 27248,5676.78 r90 top (schematic designator R1)
R2_AMP1 "Res2" RESC0603L 1349,1679 r90 top (schematic designator R2)
R2_AMP2 "Res2" RESC0603L 1532,1679 r90 top (schematic designator R2)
